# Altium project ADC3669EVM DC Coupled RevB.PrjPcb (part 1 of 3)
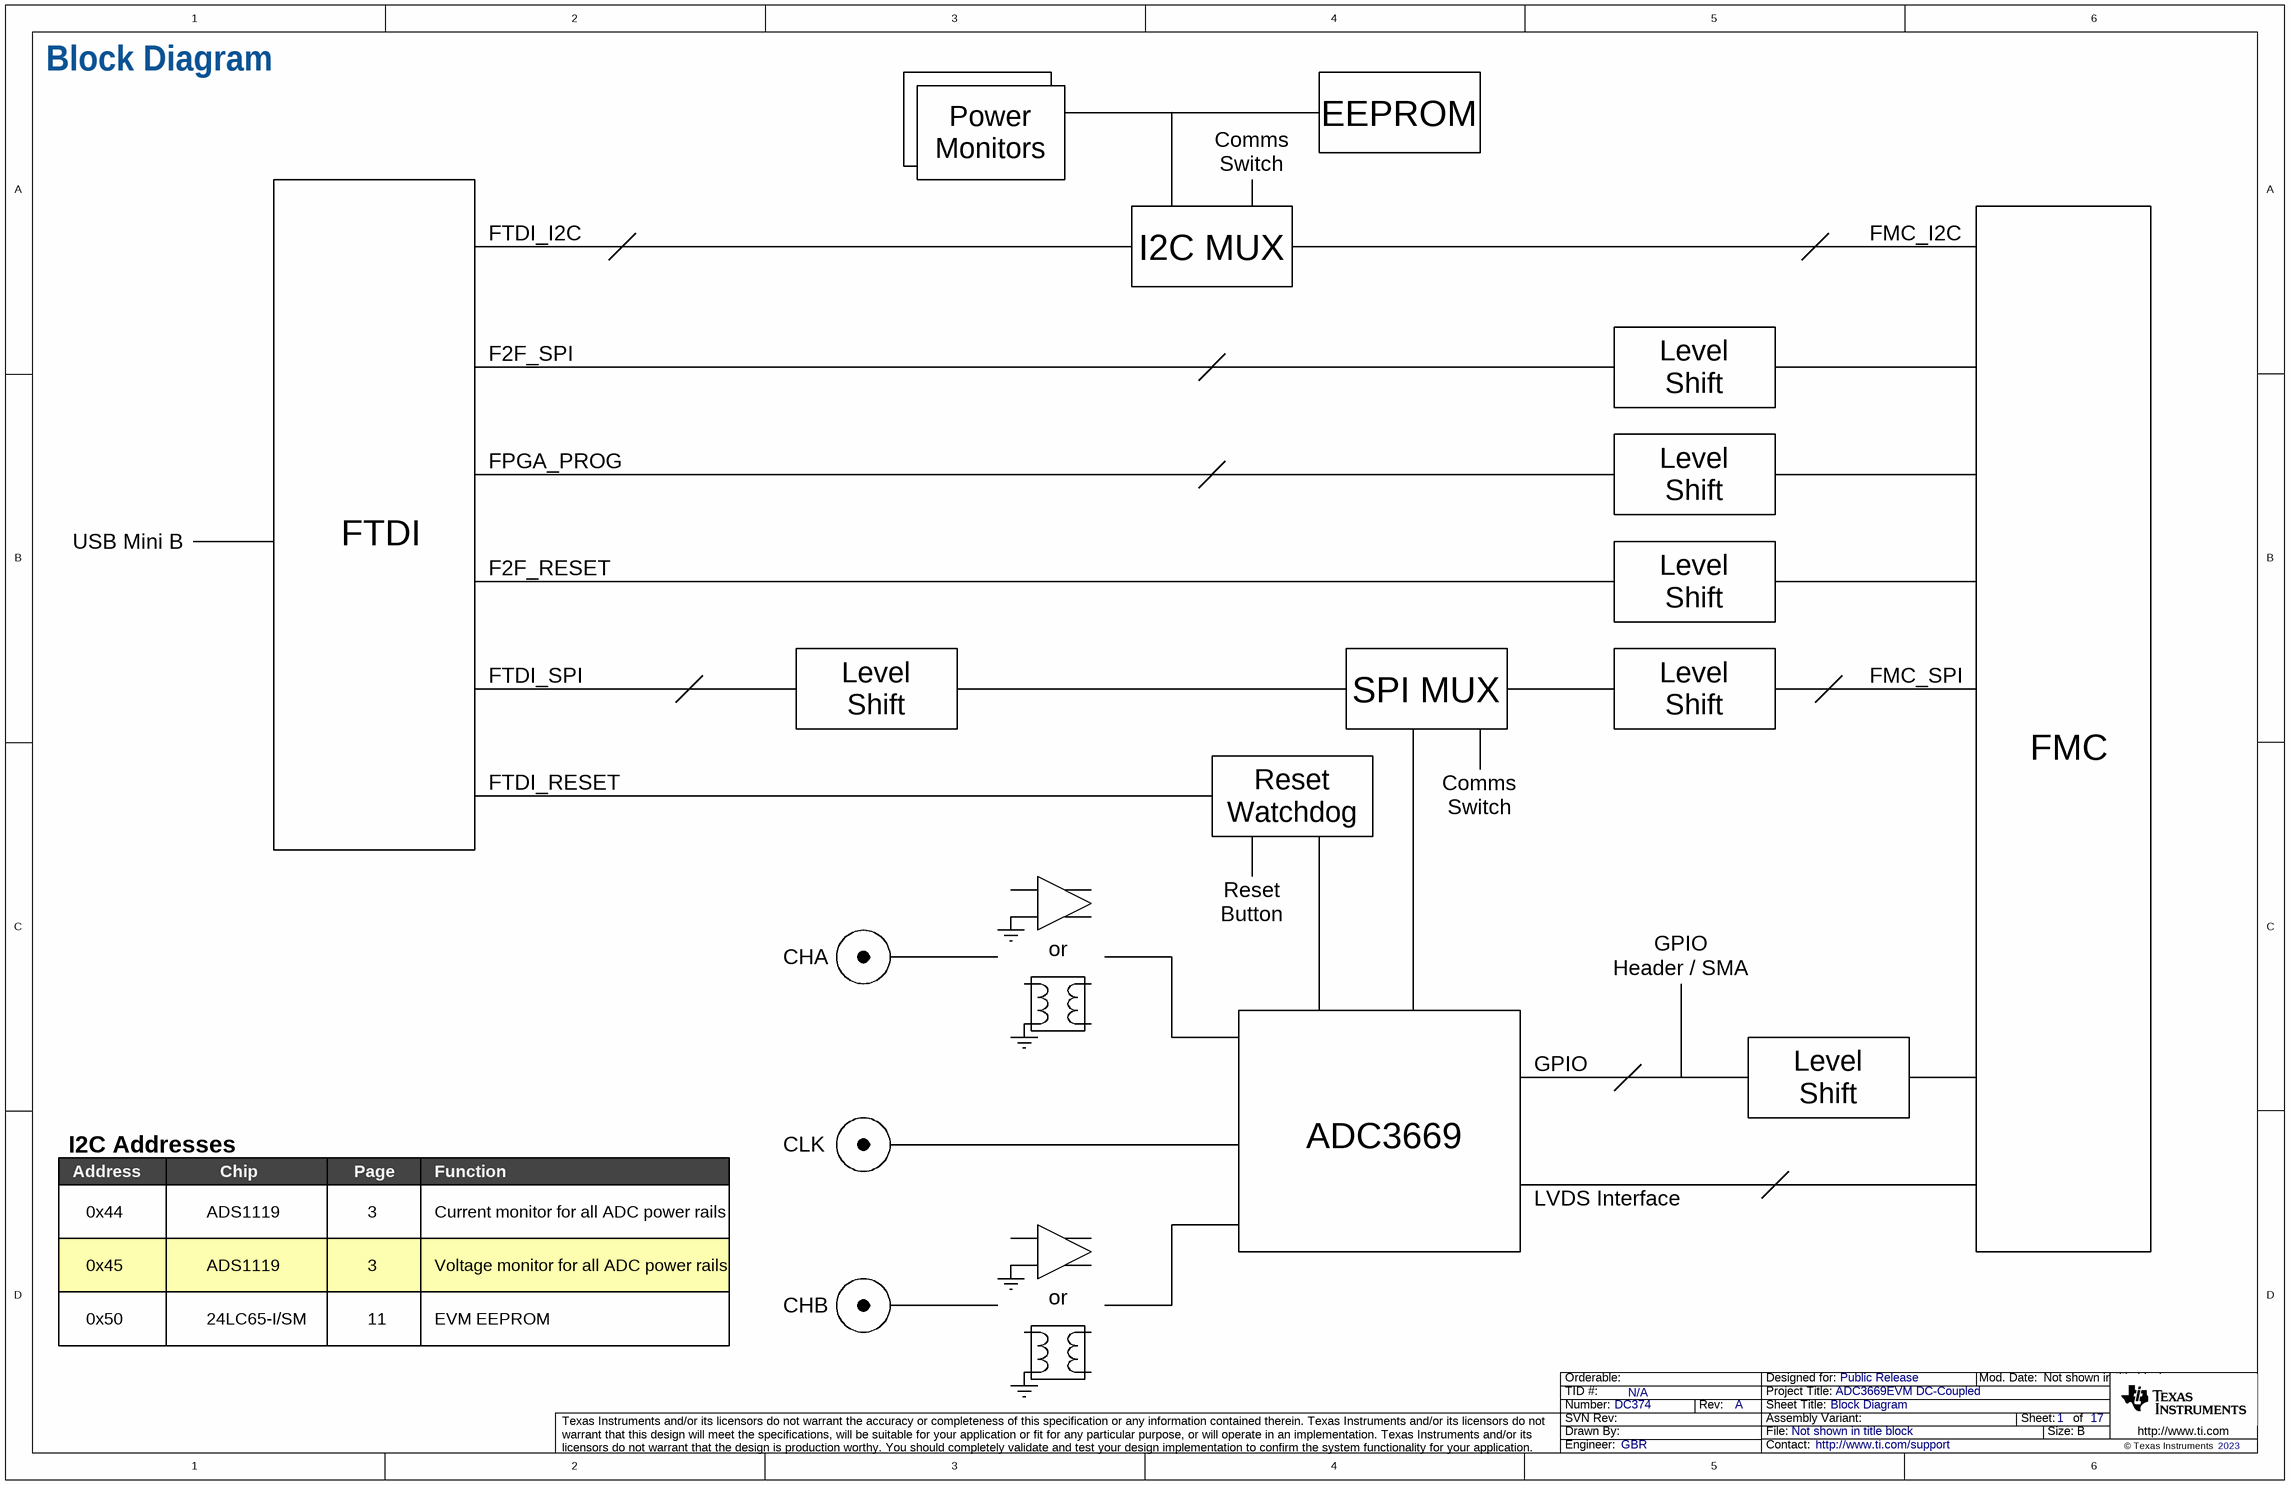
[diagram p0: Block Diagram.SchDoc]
CopyrightYear: 2023; PCB_Layout: GBR; PCB_Rev: A; PRJ_Customer: Public Release; PRJ_Engineer: GBR; PRJ_Number: DC374; PRJ_Title: ADC3669EVM DC-Coupled; SCH_Rev: A; TechSupport: http://www.ti.com/support; TID: N/A
17 sheets, 549 parts. Net scope: flat (ports and power ports of the same name join across sheets).
Board file: ADC3669EVM DC-Coupled RevB.PcbDoc
Sheets:
  Block Diagram.SchDoc
  Power Tree.SchDoc
  EVM Power.SchDoc
  ADC Power DC-DC.SchDoc
  ADC Power.SchDoc
  LMH Power DC-DC.SchDoc
  LMH Power LDO.SchDoc
  ADC IO.SchDoc
  ADC Analog Input.SchDoc
  Amplifier.SchDoc
  FMC Sections 1-7 .SchDoc
  FMC Sections 8-14.SchDoc
  FTDI USB Input.SchDoc
  Comms Level Shift.SchDoc
  I2C SPI Mux.SchDoc
  Hardware.SchDoc
  Revision History.SchDoc

## Sheet Block Diagram.SchDoc: Block Diagram
size 431 x 279 mm; Date: Not shown in title block; ApprovedBy: Not shown in title block; CheckedBy: Not shown in title block; Author: Not shown in title block; CompanyName: Not shown in title block; Engineer: Not shown in title block; Organization: Not shown in title block; Address1: Not shown in title block; Address2: Not shown in title block; Address3: Not shown in title block; Address4: Not shown in title block; DocumentNumber: 1; Revision: Use project parameter SCH_Rev; SheetNumber: 1; SheetTotal: 17; PageSetup: Record=PageOptions¦CenterHorizontal=True¦CenterVertical=True¦PrintScale=1.00¦XCorrection=1.00¦YCorrection=1.00¦PrintKind=0¦BorderSize=5000000¦LeftOffset=0¦BottomOffset=0¦Orientation=2¦PaperLength=1000¦PaperWidth=1000¦Scale=100¦PaperSource=15¦PrintQuality=600¦MediaType=1¦DitherType=10¦PaperKind=Letter¦PrintScaleMode=1

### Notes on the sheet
- Power
  Monitors
- EEPROM
- Comms
  Switch
- FTDI_I2C
- I2C MUX
- FMC_I2C
- F2F_SPI
- Level
  Shift
- FPGA_PROG
- USB Mini B
- FTDI
- F2F_RESET
- FTDI_SPI
- FMC_SPI
- SPI MUX
- FMC
- FTDI_RESET
- Reset
  Watchdog
- CHA
- or
- Reset
  Button
- GPIO
  Header / SMA
- GPIO
- Address
- I2C Addresses
- Chip
- Page
- Function
- CLK
- ADC3669
- 0x44
- ADS1119
- 3
- Current monitor for all ADC power rails
- LVDS Interface
- 0x45
- Voltage monitor for all ADC power rails
- 0x50
- 24LC65-I/SM
- 11
- EVM EEPROM
- CHB

## Sheet Power Tree.SchDoc
size 431 x 279 mm; Date: Not shown in title block; ApprovedBy: Not shown in title block; CheckedBy: Not shown in title block; Author: Not shown in title block; CompanyName: Not shown in title block; Engineer: Not shown in title block; Organization: Not shown in title block; Address1: Not shown in title block; Address2: Not shown in title block; Address3: Not shown in title block; Address4: Not shown in title block; DocumentNumber: 1; Revision: Use project parameter SCH_Rev; SheetNumber: 2; SheetTotal: 17; PageSetup: Record=PageOptions¦CenterHorizontal=True¦CenterVertical=True¦PrintScale=1.00¦XCorrection=1.00¦YCorrection=1.00¦PrintKind=0¦BorderSize=5000000¦LeftOffset=0¦BottomOffset=0¦Orientation=2¦PaperLength=1000¦PaperWidth=1000¦Scale=100¦PaperSource=15¦PrintQuality=600¦MediaType=1¦DitherType=10¦PaperKind=Letter¦PrintScaleMode=1
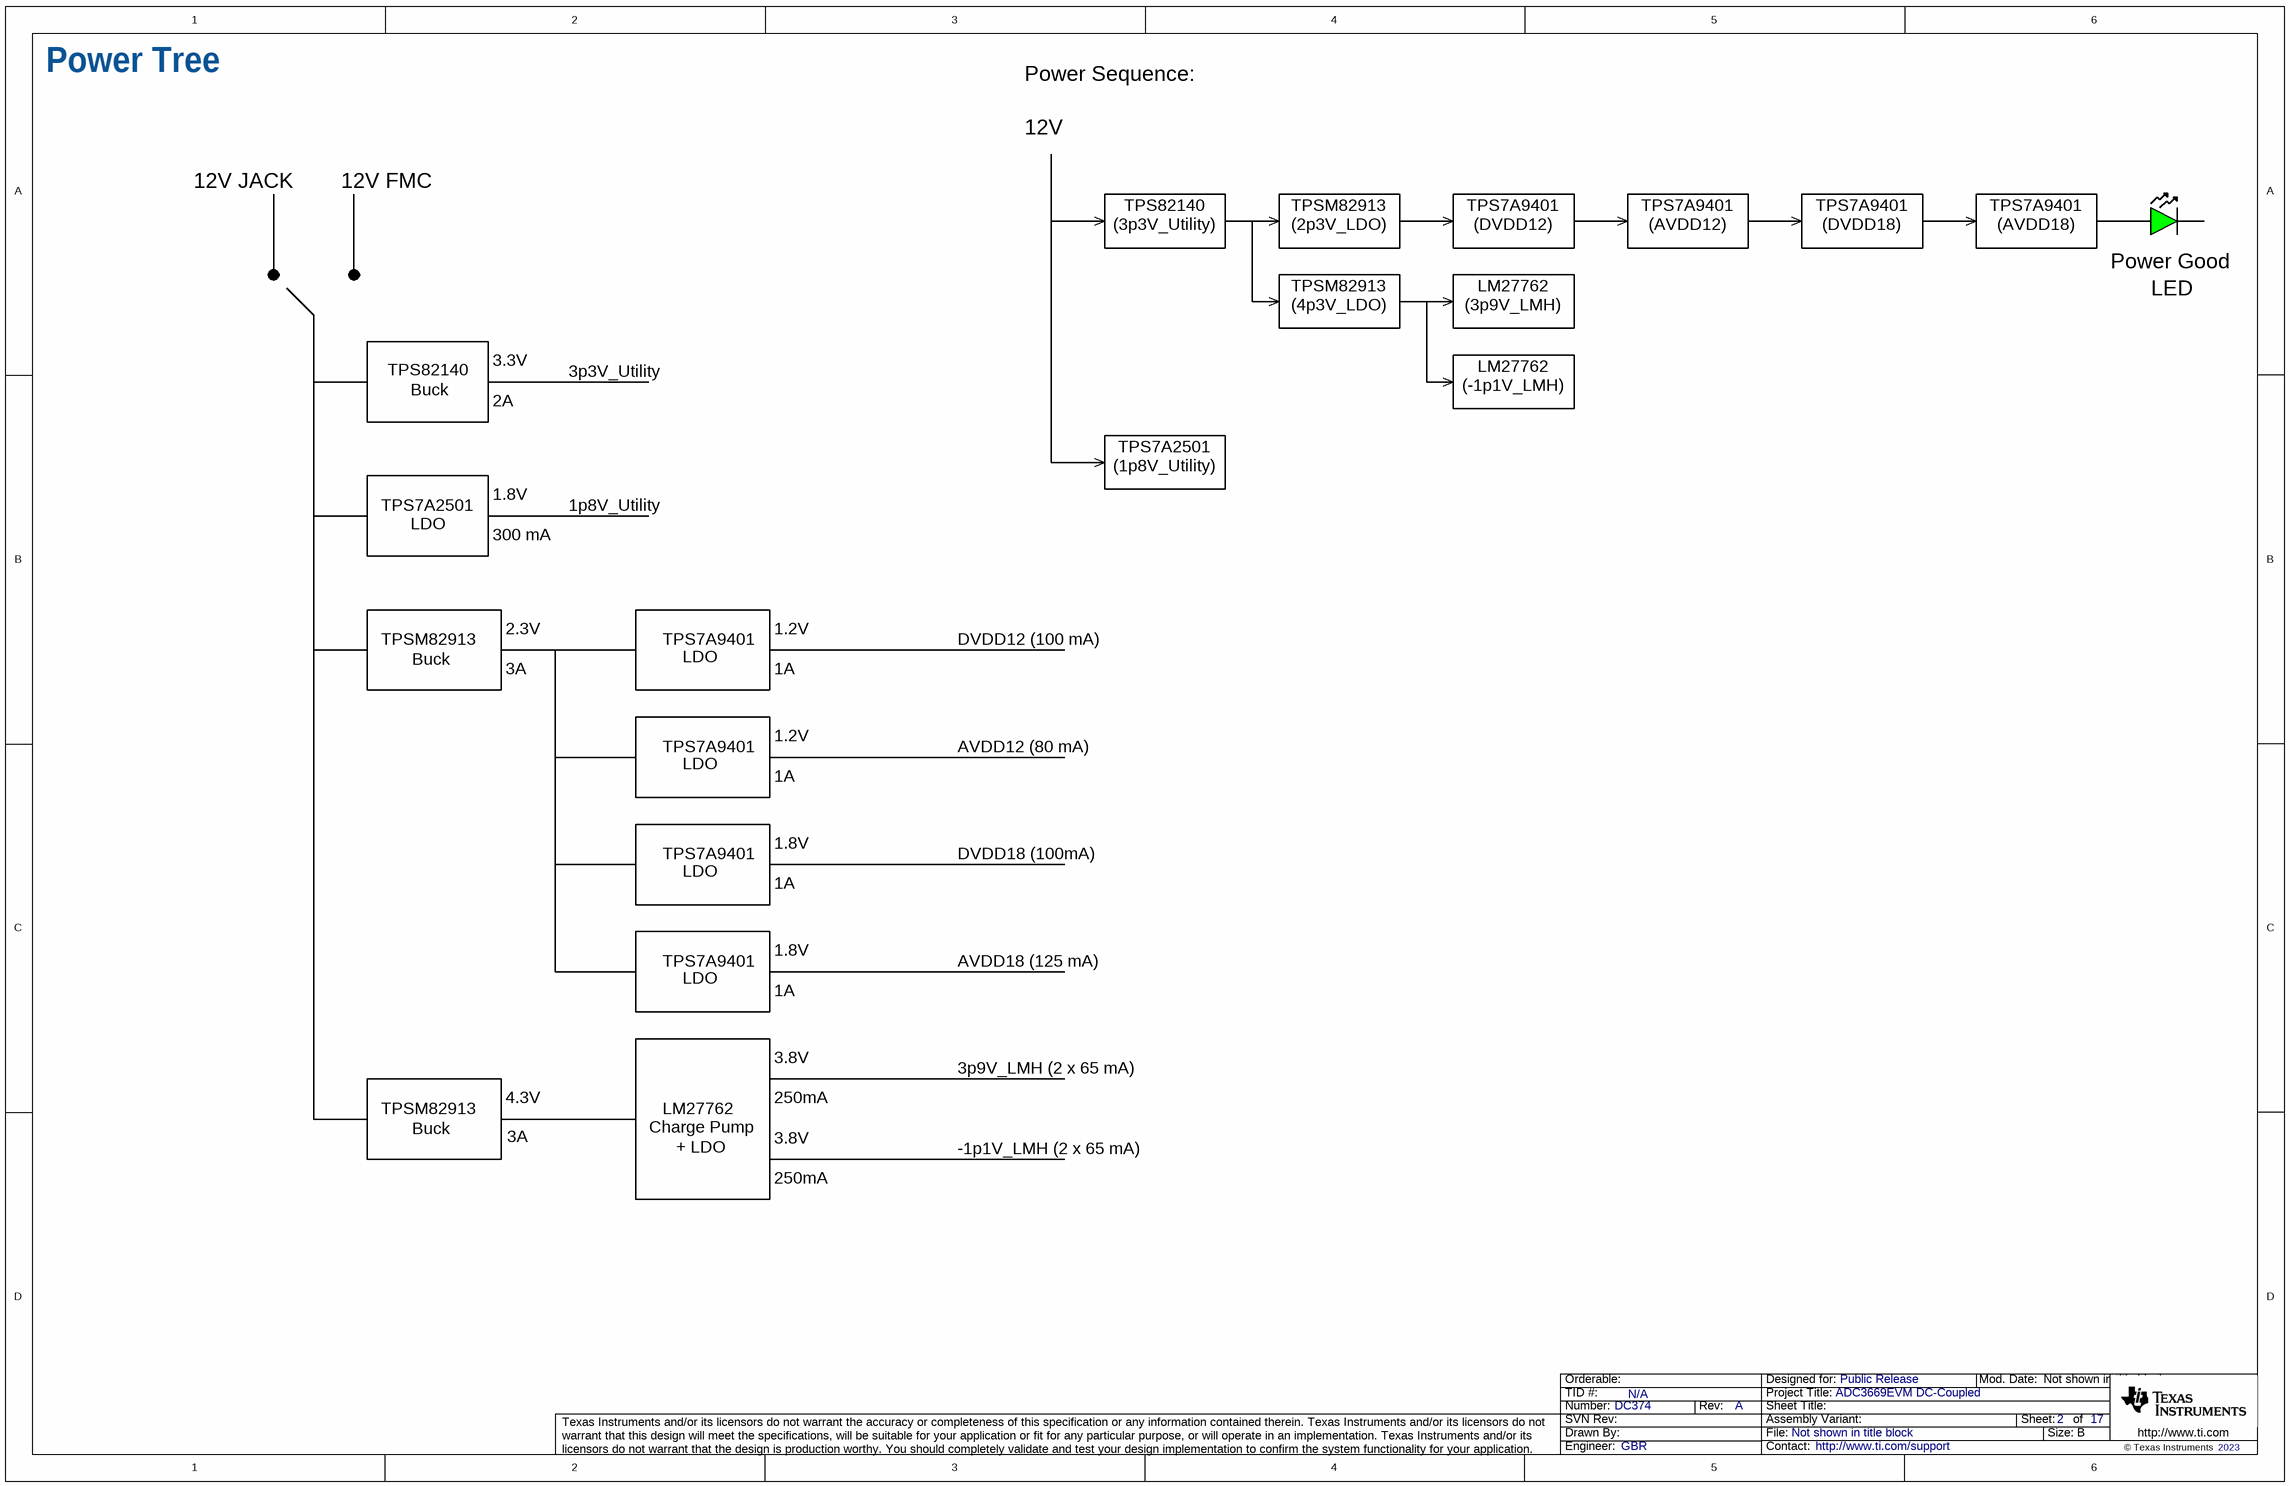
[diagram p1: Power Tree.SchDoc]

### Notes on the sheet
- Power Tree
- Power Sequence:
- 12V
- 12V JACK
- 12V FMC
- TPS82140
  (3p3V_Utility)
- TPSM82913
  (2p3V_LDO)
- TPS7A9401
  (DVDD12)
- TPS7A9401
  (AVDD12)
- TPS7A9401
  (DVDD18)
- TPS7A9401
  (AVDD18)
- Power Good
- LED
- 3.3V
- TPSM82913
  (4p3V_LDO)
- LM27762
  (3p9V_LMH)
- TPS82140
- Buck
- 2A
- 3p3V_Utility
- LM27762
  (-1p1V_LMH)
- 1.8V
- TPS7A2501
  (1p8V_Utility)
- TPS7A2501
- LDO
- 300 mA
- 1p8V_Utility
- 2.3V
- 1.2V
- TPSM82913
- 3A
- TPS7A9401
- 1A
- DVDD12 (100 mA)
- AVDD12 (80 mA)
- DVDD18 (100mA)
- AVDD18 (125 mA)
- 4.3V
- 250mA
- 3.8V
- 3p9V_LMH (2 x 65 mA)
- Charge Pump
- LM27762
- + LDO
- -1p1V_LMH (2 x 65 mA)

## Sheet EVM Power.SchDoc: EVM Power
size 431 x 279 mm; Date: Not shown in title block; ApprovedBy: Not shown in title block; CheckedBy: Not shown in title block; Author: Not shown in title block; CompanyName: Not shown in title block; Engineer: Not shown in title block; Organization: Not shown in title block; Address1: Not shown in title block; Address2: Not shown in title block; Address3: Not shown in title block; Address4: Not shown in title block; DocumentNumber: 1; Revision: Use project parameter SCH_Rev; SheetNumber: 3; SheetTotal: 17; PageSetup: Record=PageOptions¦CenterHorizontal=True¦CenterVertical=True¦PrintScale=1.00¦XCorrection=1.00¦YCorrection=1.00¦PrintKind=0¦BorderSize=5000000¦LeftOffset=0¦BottomOffset=0¦Orientation=2¦PaperLength=1000¦PaperWidth=1000¦Scale=100¦PaperSource=15¦PrintQuality=600¦MediaType=1¦DitherType=10¦PaperKind=Letter¦PrintScaleMode=1
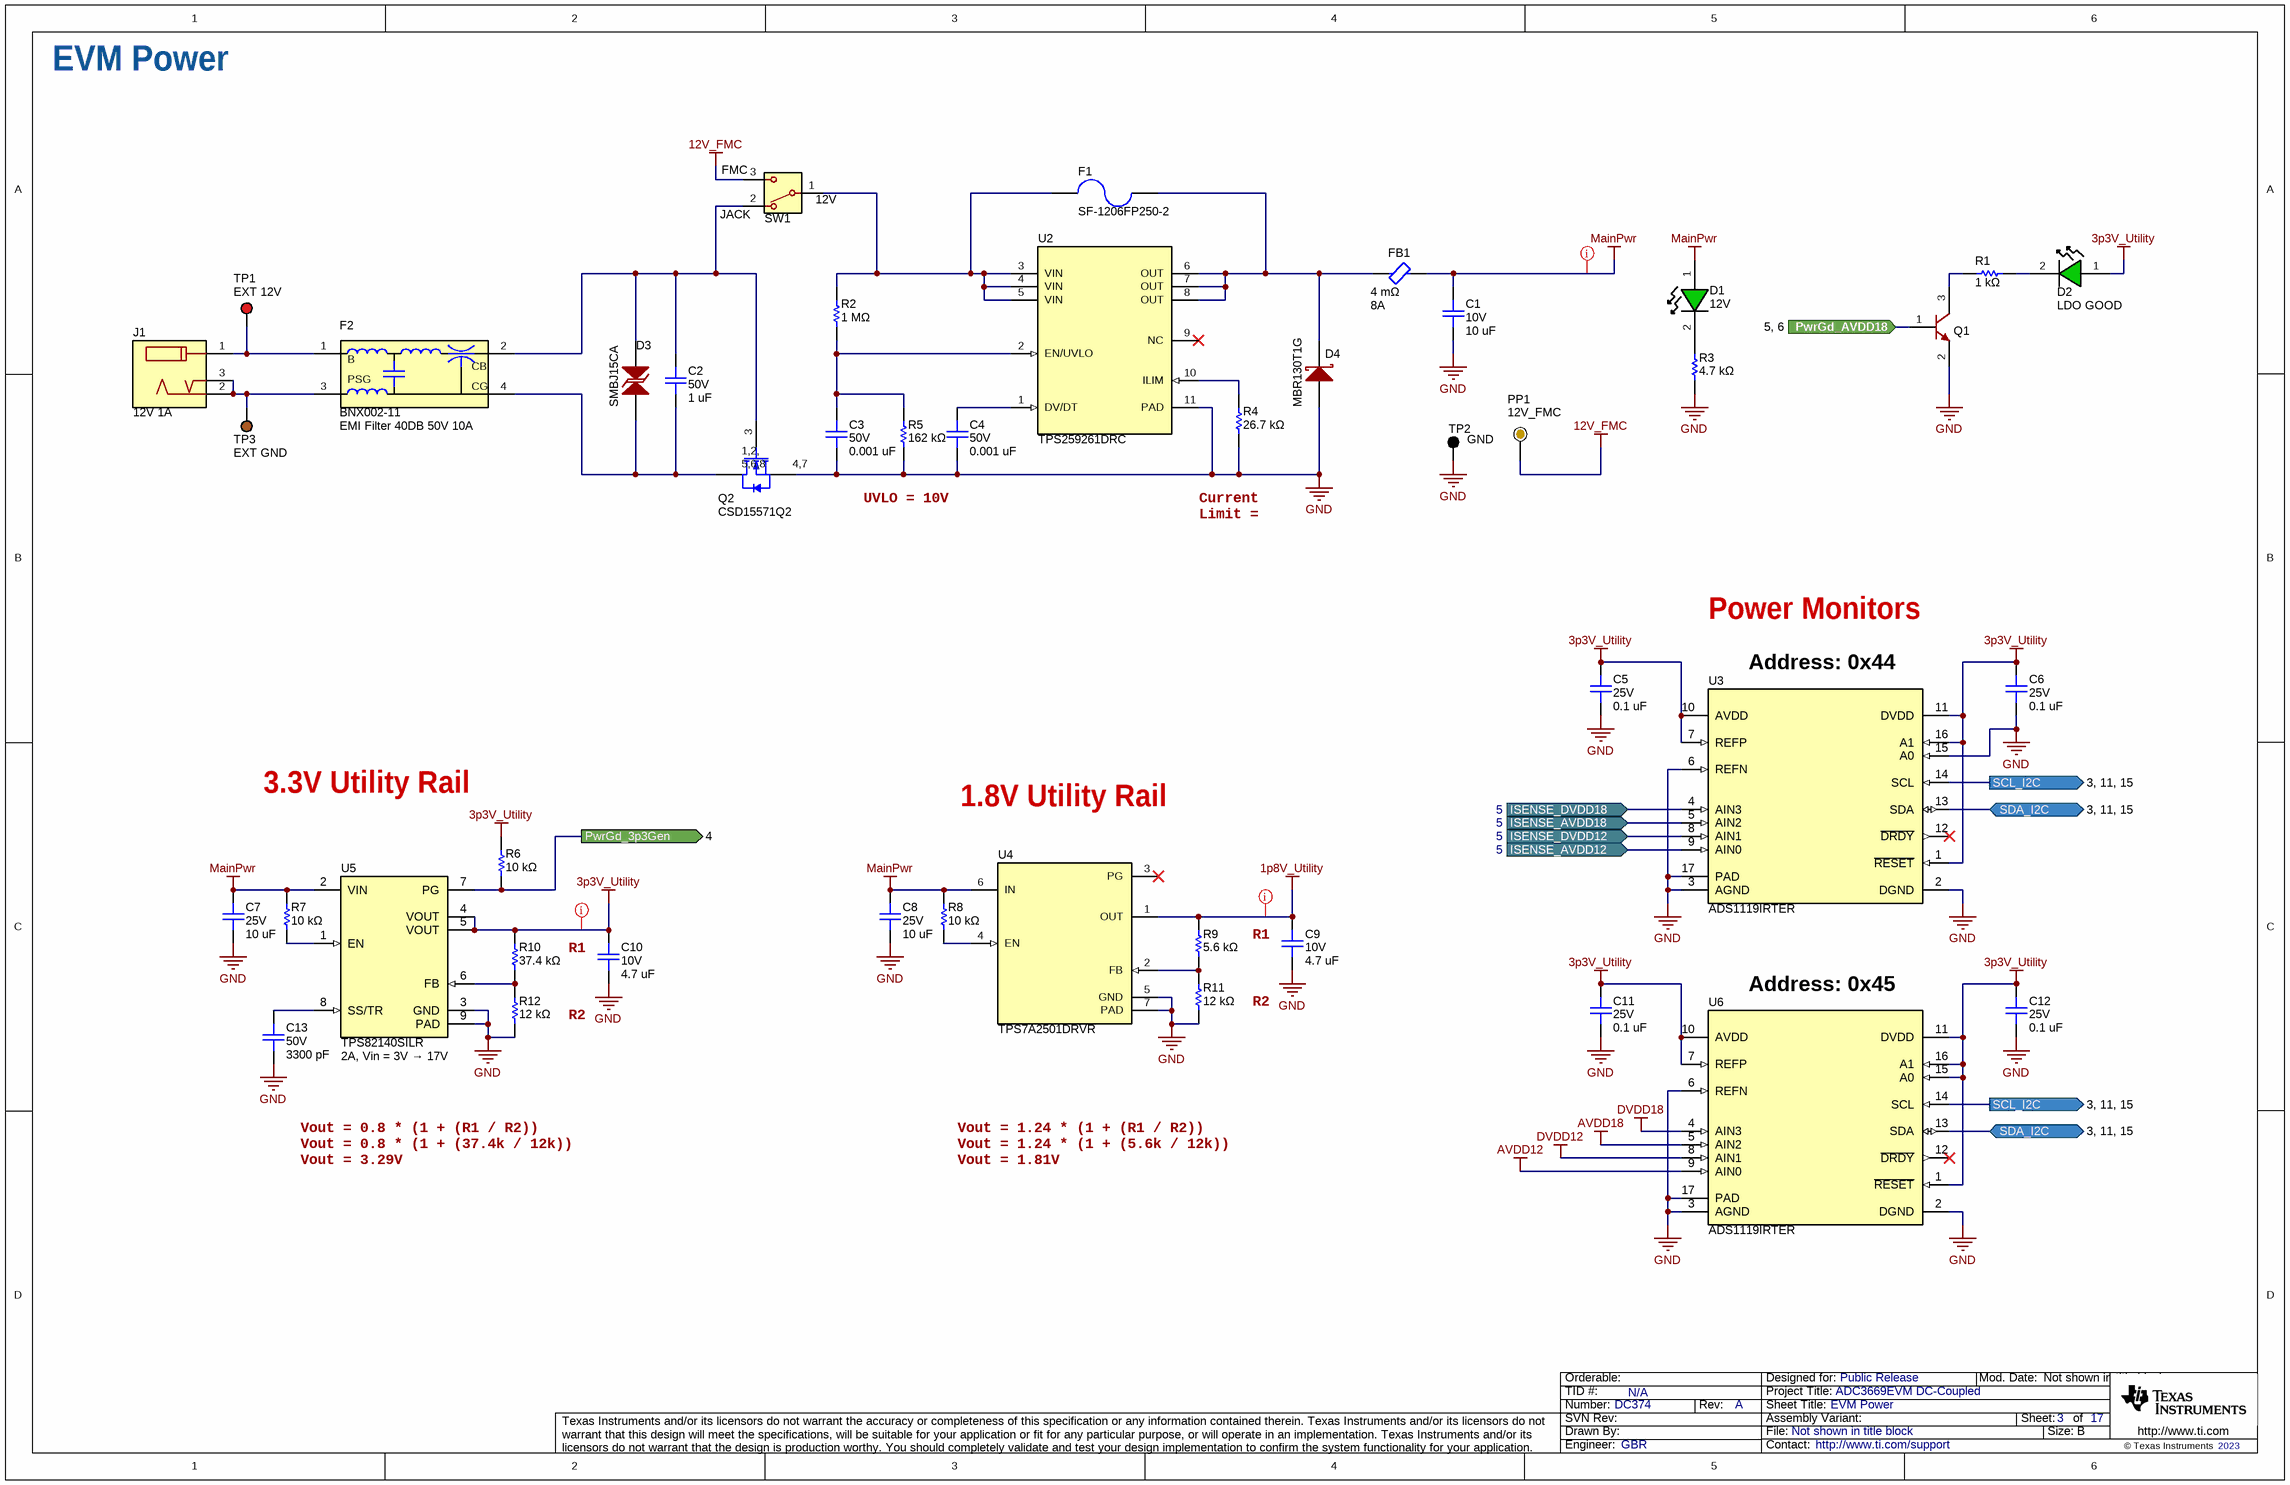
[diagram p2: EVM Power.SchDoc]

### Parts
C1  value 10 uF  Voltage - Rated: 10V  [0402L_cap]  (hidden comment: 0402ZD106MAT2A)
C2  value 1 uF  Voltage - Rated: 50V  [0603L_cap]  (hidden comment: 06035C105KAT2A)
C3  value 0.001 uF  Voltage - Rated: 50V  [0603L_cap]  (hidden comment: CGA3E2X7R1H102K080AA)
C4  value 0.001 uF  Voltage - Rated: 50V  [0603L_cap]  (hidden comment: CGA3E2X7R1H102K080AA)
C5  value 0.1 uF  Voltage - Rated: 25V  [0402L_cap]  (hidden comment: C1005X5R1E104K050BC)
C6  value 0.1 uF  Voltage - Rated: 25V  [0402L_cap]  (hidden comment: C1005X5R1E104K050BC)
C7  value 10 uF  Voltage - Rated: 25V  [0805L_cap]  (hidden comment: 08053D106KAT4A)
C8  value 10 uF  Voltage - Rated: 25V  [0805L_cap]  (hidden comment: 08053D106KAT4A)
C9  value 4.7 uF  Voltage - Rated: 10V  [0402L_cap]  (hidden comment: C1005X5R1A475K050BE)
C10  value 4.7 uF  Voltage - Rated: 10V  [0402L_cap]  (hidden comment: C1005X5R1A475K050BE)
C11  value 0.1 uF  Voltage - Rated: 25V  [0402L_cap]  (hidden comment: C1005X5R1E104K050BC)
C12  value 0.1 uF  Voltage - Rated: 25V  [0402L_cap]  (hidden comment: C1005X5R1E104K050BC)
C13  value 3300 pF  Voltage - Rated: 50V  [0402L_cap]  (hidden comment: 04025C332K4T2A)
D1  Text1: 12V  [LED_LTST-C190-Green]  (hidden comment: LTST-C191TGKT)
D2  Text1: LDO GOOD  [LED_LTST-C190-Green]  (hidden comment: LTST-C191TGKT)
D3  SMBJ15CA  [SMBJ15CA]
D4  MBR130T1G  [SOD-123]
F1  SF-1206FP250-2  [SF-1206F500M-2_1206]
F2  BNX002-11  Text1: EMI Filter 40DB 50V 10A  [FIL_BNX002-11]
FB1  Current: 8A  DCR: 4 mΩ  [0603L]  (hidden comment: BLE18PS080SN1D)
J1  Text1: 12V 1A  [RAPC722X]  (hidden comment: RAPC722X)
PP1  Text1: 12V_FMC  [ProbePoint_TH_40mil]  (hidden comment: Probe Point)  (no BOM)
Q1  MMBT3904WT1G  [SOT-323]  (value not drawn)
Q2  CSD15571Q2  [DQK0006C]
R1  value 1 kΩ  [0402L]  (hidden comment: ERA-2AED102X)
R2  value 1 MΩ  [0402L]  (hidden comment: ERJ-2RKF1004X)
R3  value 4.7 kΩ  [0402L]  (hidden comment: ERJ-H2RF4701X)
R4  value 26.7 kΩ  [0402L]  (hidden comment: ERA-2APB2672X)
R5  value 162 kΩ  [0402L]  (hidden comment: ERJ-2RKF1623X)
R6  value 10 kΩ  [0402L]  (hidden comment: ERJ-2RKF1002X)
R7  value 10 kΩ  [0402L]  (hidden comment: ERJ-2RKF1002X)
R8  value 10 kΩ  [0402L]  (hidden comment: ERJ-2RKF1002X)
R9  value 5.6 kΩ  [0402L]  (hidden comment: ERA-2APB562X)
R10  value 37.4 kΩ  [0402L]  (hidden comment: ERA-2AEB3742X)
R11  value 12 kΩ  [0402L]  (hidden comment: ERA-2ARB123X)
R12  value 12 kΩ  [0402L]  (hidden comment: ERA-2ARB123X)
SW1  Text1: 12V  Text2: JACK  Text3: FMC  [450301014042]  (hidden comment: cmp00353)
TP1  Text1: EXT 12V  [Keystone5010]  (hidden comment: 5010)
TP2  Text1: GND  [Keystone5011]  (hidden comment: cmp00041)
TP3  Text1: EXT GND  [Keystone5125]  (hidden comment: 5125)
U2  TPS259261DRC  [DRC0010J]
U3  ADS1119IRTER  [RTE0016D]
U4  TPS7A2501DRVR  [DRV0006A]
U5  TPS82140SILR  Text1: 2A, Vin = 3V → 17V  [SIL0008D]
U6  ADS1119IRTER  [RTE0016D]

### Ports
ISENSE_AVDD12 (in, see 5), ISENSE_AVDD18 (in, see 5), ISENSE_DVDD12 (in, see 5), ISENSE_DVDD18 (in, see 5), PwrGd_3p3Gen (out, see 4), PwrGd_AVDD18 (in, see 5, 6), SCL_I2C (out, see 3, 11, 15), SDA_I2C (bidir, see 3, 11, 15)

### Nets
1p8V_Utility: C9.2 R9.2 U4.1(OUT)
3p3V_Utility: C5.2 C6.2 C10.2 C11.2 C12.2 D2.1(A) R6.2 R10.2 U3.1(~{RESET}) U3.7(REFP) U3.10(AVDD) U3.11(DVDD) U3.16(A1) U5.4(VOUT) U5.5(VOUT) U6.1(~{RESET}) U6.7(REFP) U6.10(AVDD) U6.11(DVDD) U6.15(A0) U6.16(A1)
12V_FMC: PP1.1 SW1.3
AVDD12: U6.9(AIN0)
AVDD18: U6.5(AIN2)
DVDD12: U6.8(AIN1)
DVDD18: U6.4(AIN3)
GND: C1.1 C3.1 C4.1 C5.1 C6.1 C7.1 C8.1 C9.1 C10.1 C11.1 C12.1 C13.1 D4.2(A) Q1.2(E) Q2.4,7(S) R3.1 R4.1 R5.1 R11.1 R12.1 TP2.1 U2.11(PAD) U3.2(DGND) U3.3(AGND) U3.6(REFN) U3.15(A0) U3.17(PAD) U4.5(GND) U4.7(PAD) U5.3(GND) U5.9(PAD) U6.2(DGND) U6.3(AGND) U6.6(REFN) U6.17(PAD)
MainPwr: C1.2 C7.2 C8.2 D1.1(A) FB1.2 R7.2 R8.2 U4.6(IN) U5.2(VIN)
ISENSE_AVDD12: U3.9(AIN0) ; port ISENSE_AVDD12
ISENSE_AVDD18: U3.5(AIN2) ; port ISENSE_AVDD18
ISENSE_DVDD12: U3.8(AIN1) ; port ISENSE_DVDD12
ISENSE_DVDD18: U3.4(AIN3) ; port ISENSE_DVDD18
PwrGd_3p3Gen: R6.1 U5.7(PG) ; port PwrGd_3p3Gen
PwrGd_AVDD18: Q1.1(B) ; port PwrGd_AVDD18
SCL_I2C: U3.14(SCL) U6.14(SCL) ; port SCL_I2C
SDA_I2C: U3.13(SDA) U6.13(SDA) ; port SDA_I2C
NetC2_1: C2.1 D3.2 F2.2(CB) Q2.3(G) SW1.2(COMM)
NetC2_2: C2.2 D3.1 F2.4(CG) Q2.1,2,5,6,8(D)
NetC3_2: C3.2 R2.1 R5.2 U2.2(EN/UVLO)
NetC4_2: C4.2 U2.1(DV/DT)
NetC13_2: C13.2 U5.8(SS/TR)
NetD1_2: D1.2(K) R3.2
NetD2_2: D2.2(K) R1.1
NetD4_1: D4.1(K) F1.1 FB1.1 U2.6(OUT) U2.7(OUT) U2.8(OUT)
NetF1_2: F1.2 R2.2 SW1.1 U2.3(VIN) U2.4(VIN) U2.5(VIN)
NetF2_1: F2.1(B) J1.1 TP1.1
NetF2_3: F2.3(PSG) J1.2 J1.3 TP3.1
NetQ1_3: Q1.3(C) R1.2
NetR4_2: R4.2 U2.10(ILIM)
NetR7_1: R7.1 U5.1(EN)
NetR8_1: R8.1 U4.4(EN)
NetR9_1: R9.1 R11.2 U4.2(FB)
NetR10_1: R10.1 R12.2 U5.6(FB)

Not connected (* = marked no-connect by the designer): U2 9(NC)*; U3 12(~{DRDY})*; U4 3(PG)*; U6 12(~{DRDY})*

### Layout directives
net class Power: MainPwr
net class Power; net class GenPwr: 1p8V_Utility, 3p3V_Utility

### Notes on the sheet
- UVLO = 10V
- Current Limit = 1.5A
- Power Monitors
- (near U3) Address: 0x44
- (near R6) 3.3V Utility Rail
- 1.8V Utility Rail
- (near C10) R1
- (near C9) R1
- R2
- (near U6) Address: 0x45
- Vout = 0.8 * (1 + (R1 / R2))
  Vout = 0.8 * (1 + (37.4k / 12k))
  Vout = 3.29V
- Vout = 1.24 * (1 + (R1 / R2))
  Vout = 1.24 * (1 + (5.6k / 12k))
  Vout = 1.81V

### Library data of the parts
C1 = capcc09406: CAP CER 10UF 10V X5R 0402; Manufacturer: KYOCERA AVX; CompType: Capacitor Ceramic; Tolerance: ±20%; SizeX_mm: 1; SizeY_mm: 0.5; SizeZ_mm: 0.7
C2 = capcc02732: CAP CER 1UF 50V X7R 0603; Manufacturer: KYOCERA AVX; CompType: Capacitor Ceramic; Tolerance: ±10%; SizeX_mm: 1.6; SizeY_mm: 0.81; SizeZ_mm: 0.5
C3 C4 = capcc03751: CAP CER 1000PF 50V X7R 0603; Manufacturer: TDK Corporation; CompType: Capacitor Ceramic; Tolerance: ±10%; SizeX_mm: 1.6; SizeY_mm: 0.8; SizeZ_mm: 0.9
C5 C6 C11 C12 = capcc01263: CAP CER 0.1UF 25V X5R 0402; Manufacturer: TDK Corporation; CompType: Capacitor Ceramic; Tolerance: ±10%; SizeX_mm: 1; SizeY_mm: 0.5; SizeZ_mm: 0.55
C7 C8 = capcc03515: CAP CER 10UF 25V X5R 0805; Manufacturer: KYOCERA AVX; CompType: Capacitor Ceramic; Tolerance: ±10%; SizeX_mm: 2.01; SizeY_mm: 1.25; SizeZ_mm: 1.52
C9 C10 = capcc03139: CAP CER 4.7UF 10V X5R 0402; Manufacturer: TDK Corporation; CompType: Capacitor Ceramic; Tolerance: ±10%; SizeX_mm: 1; SizeY_mm: 0.5; SizeZ_mm: 0.7
C13 = capcc04791: CAP CER 3300PF 50V X7R 0402; Manufacturer: KYOCERA AVX; CompType: Capacitor Ceramic; Tolerance: ±10%; SizeX_mm: 1; SizeY_mm: 0.5; SizeZ_mm: 0.56
D1 D2 = cmp00247: LED GREEN CLEAR CHIP SMD; Manufacturer: Lite-On Inc.; Current Rating (Amps): 20mA; Voltage - Forward (Vf) (Typ): 3.2V; SizeX_mm: 1.6; SizeY_mm: 0.8; SizeZ_mm: 0.65
D3 = cmp00440: 24.4V Clamp 24.6A Ipp Tvs Diode; Manufacturer: Littlefuse; CompType: Diode TVS
D4 = cmp00438: DIODE SCHOTTKY 30V 1A SOD123; Manufacturer: Onsemi; Alt Manufacturer: Rohm Semiconductor; Alt PartNumber: RB160M-30TR
F1 = cmp00082: FUSE BOARD MOUNT 2.5A 32VDC 1206; Manufacturer: Bourns Inc.; Voltage Rating - DC: 32 V; SizeX_mm: 3.1; SizeY_mm: 1.55; SizeZ_mm: 0.6
F2 = cmp00325: EMI Filter Circuits 40 DB 50V 10A; Manufacturer: Murata Electronics
FB1 = dcp00004: 8.5 Ohms @ 100 MHz 1 Power Line Ferrite Bead 0603 (1608 Metric) 8A 4mOhm; Manufacturer: Murata; Impedance: 8.5 Ω; SizeX_mm: 1.6; SizeY_mm: 0.8
J1 = RAPC722X: Power Jack, mini, 2.1mm OD, R/A, TH; Manufacturer: Switchcraft; UniqueID: cmp00022
PP1 = Probe Point: Probe Point that can be used in lue of a test point; UniqueID: cmp00025
Q1 = cmp00439: Bipolar (BJT) Transistor NPN 40 V 200 mA 300MHz 300 mW; PartNumber: SMMBT3904LT1G; Manufacturer: Onsemi
Q2 = cmp00159: MOSFET, N-CH, 20 V, 10 A; Manufacturer: Texas Instruments; CompType: FET
R1 = RSMD040200005: RES SMD 1K OHM 0.5% 1/16W 0402; Manufacturer: Panasonic Electronic Components; CompType: Resistor SMD; Power (Watts): 0.063W, 1/16W; Temperature Coefficient: ±25ppm/°C; SizeX_mm: 1; SizeY_mm: 0.5; SizeZ_mm: 0.4
R2 = RSMD040200026: RES SMD 1M OHM 1% 1/10W 0402; Manufacturer: Panasonic Electronic Components; CompType: Resistor SMD; Power (Watts): 0.1W, 1/10W; Temperature Coefficient: ±100ppm/°C; SizeX_mm: 1; SizeY_mm: 0.5; SizeZ_mm: 0.4
R3 = RSMD040202592: RES 4.7K OHM 1% 1/10W 0402; Manufacturer: Panasonic Electronic Components; CompType: Resistor SMD; Power (Watts): 0.1W, 1/10W; Temperature Coefficient: ±100ppm/°C; SizeX_mm: 1; SizeY_mm: 0.5; SizeZ_mm: 0.4
R4 = RSMD040201732: RES SMD 26.7KOHM 0.1% 1/16W 0402; Manufacturer: Panasonic Electronic Components; CompType: Resistor SMD; Power (Watts): 0.063W, 1/16W; Temperature Coefficient: ±15ppm/°C; SizeX_mm: 1; SizeY_mm: 0.5; SizeZ_mm: 0.4
R5 = RSMD040200944: RES SMD 162K OHM 1% 1/10W 0402; Manufacturer: Panasonic Electronic Components; CompType: Resistor SMD; Power (Watts): 0.1W, 1/10W; Temperature Coefficient: ±100ppm/°C; SizeX_mm: 1; SizeY_mm: 0.5; SizeZ_mm: 0.4
R6-R8 = RSMD040200314: RES SMD 10K OHM 1% 1/10W 0402; Manufacturer: Panasonic Electronic Components; CompType: Resistor SMD; Power (Watts): 0.1W, 1/10W; Temperature Coefficient: ±100ppm/°C; SizeX_mm: 1; SizeY_mm: 0.5; SizeZ_mm: 0.4
R9 = RSMD040202967: RES SMD 5.6K OHM 0.1% 1/16W 0402; Manufacturer: Panasonic Electronic Components; CompType: Resistor SMD; Power (Watts): 0.063W, 1/16W; Temperature Coefficient: ±15ppm/°C; SizeX_mm: 1; SizeY_mm: 0.5; SizeZ_mm: 0.4
R10 = RSMD040202418: RES SMD 37.4KOHM 0.1% 1/16W 0402; Manufacturer: Panasonic Electronic Components; CompType: Resistor SMD; Power (Watts): 0.063W, 1/16W; Temperature Coefficient: ±25ppm/°C; SizeX_mm: 1; SizeY_mm: 0.5; SizeZ_mm: 0.4
R11 R12 = RSMD040200520: RES SMD 12K OHM 0.1% 1/16W 0402; Manufacturer: Panasonic Electronic Components; CompType: Resistor SMD; Power (Watts): 0.063W, 1/16W; Temperature Coefficient: ±10ppm/°C; SizeX_mm: 1; SizeY_mm: 0.5; SizeZ_mm: 0.4
SW1 = cmp00353: Switch Slide SPDT 12V, 500mA; Manufacturer: Wurth Elektronik
TP1 = cmp00040: Test Point, Multipurpose, Red, TH; Manufacturer: Keystone
TP2 = cmp00041: Test Point, Multipurpose, Black, TH; PartNumber: 5011; Manufacturer: Keystone
TP3 = cmp00047: Test Point, Multipurpose, Brown, TH; Manufacturer: Keystone
U2 = cmp00157: 12V, 5A, 30mΩ eFuse with Adjustable +/-15% Accurate Current Limit, DRC0010J (VSON-10); Manufacturer: Texas Instruments; Text1: Rilim=(IOL-0.7)/30µ
U3 U6 = ADS1119IRTER: 16-Bit, 4-Channel, 1-kSPS, Delta-Sigma ADC with I2C Interface, RTE0016D (WQFN-16); Alternate PartNumber: ADS1119IRTET; Alternate Manufacturer: Texas Instruments; SizeAreaWB_mm2: 16; SizeZ_mm: 0.8; SizeX_mm: 3; SizeArea_mm2: 9; AEC Qualified: N; AEC Category: Q200
U4 = cmp00251: 300-mA, 18-V, Ultra-Low IQ, Low-Dropout Linear Voltage Regulator With Power-Good; Manufacturer: Texas Instruments; CompType: LDO
U5 = TPS82140SILR: 17V Input 2A Synchronous Step-Down Converter MicroSiP Module With Integrated Inductor, SIL0008D (uSIP-8); Manufacturer: Texas Instruments; Alternate PartNumber: TPS82140SILT; CompType: Switcher

## Sheet ADC Power DC-DC.SchDoc
size 431 x 279 mm; Date: Not shown in title block; ApprovedBy: Not shown in title block; CheckedBy: Not shown in title block; Author: Not shown in title block; CompanyName: Not shown in title block; Engineer: Not shown in title block; Organization: Not shown in title block; Address1: Not shown in title block; Address2: Not shown in title block; Address3: Not shown in title block; Address4: Not shown in title block; DocumentNumber: 1; Revision: Use project parameter SCH_Rev; SheetNumber: 4; SheetTotal: 17; PageSetup: Record=PageOptions¦CenterHorizontal=True¦CenterVertical=True¦PrintScale=1.00¦XCorrection=1.00¦YCorrection=1.00¦PrintKind=0¦BorderSize=5000000¦LeftOffset=0¦BottomOffset=0¦Orientation=2¦PaperLength=1000¦PaperWidth=1000¦Scale=100¦PaperSource=15¦PrintQuality=600¦MediaType=1¦DitherType=10¦PaperKind=Letter¦PrintScaleMode=1
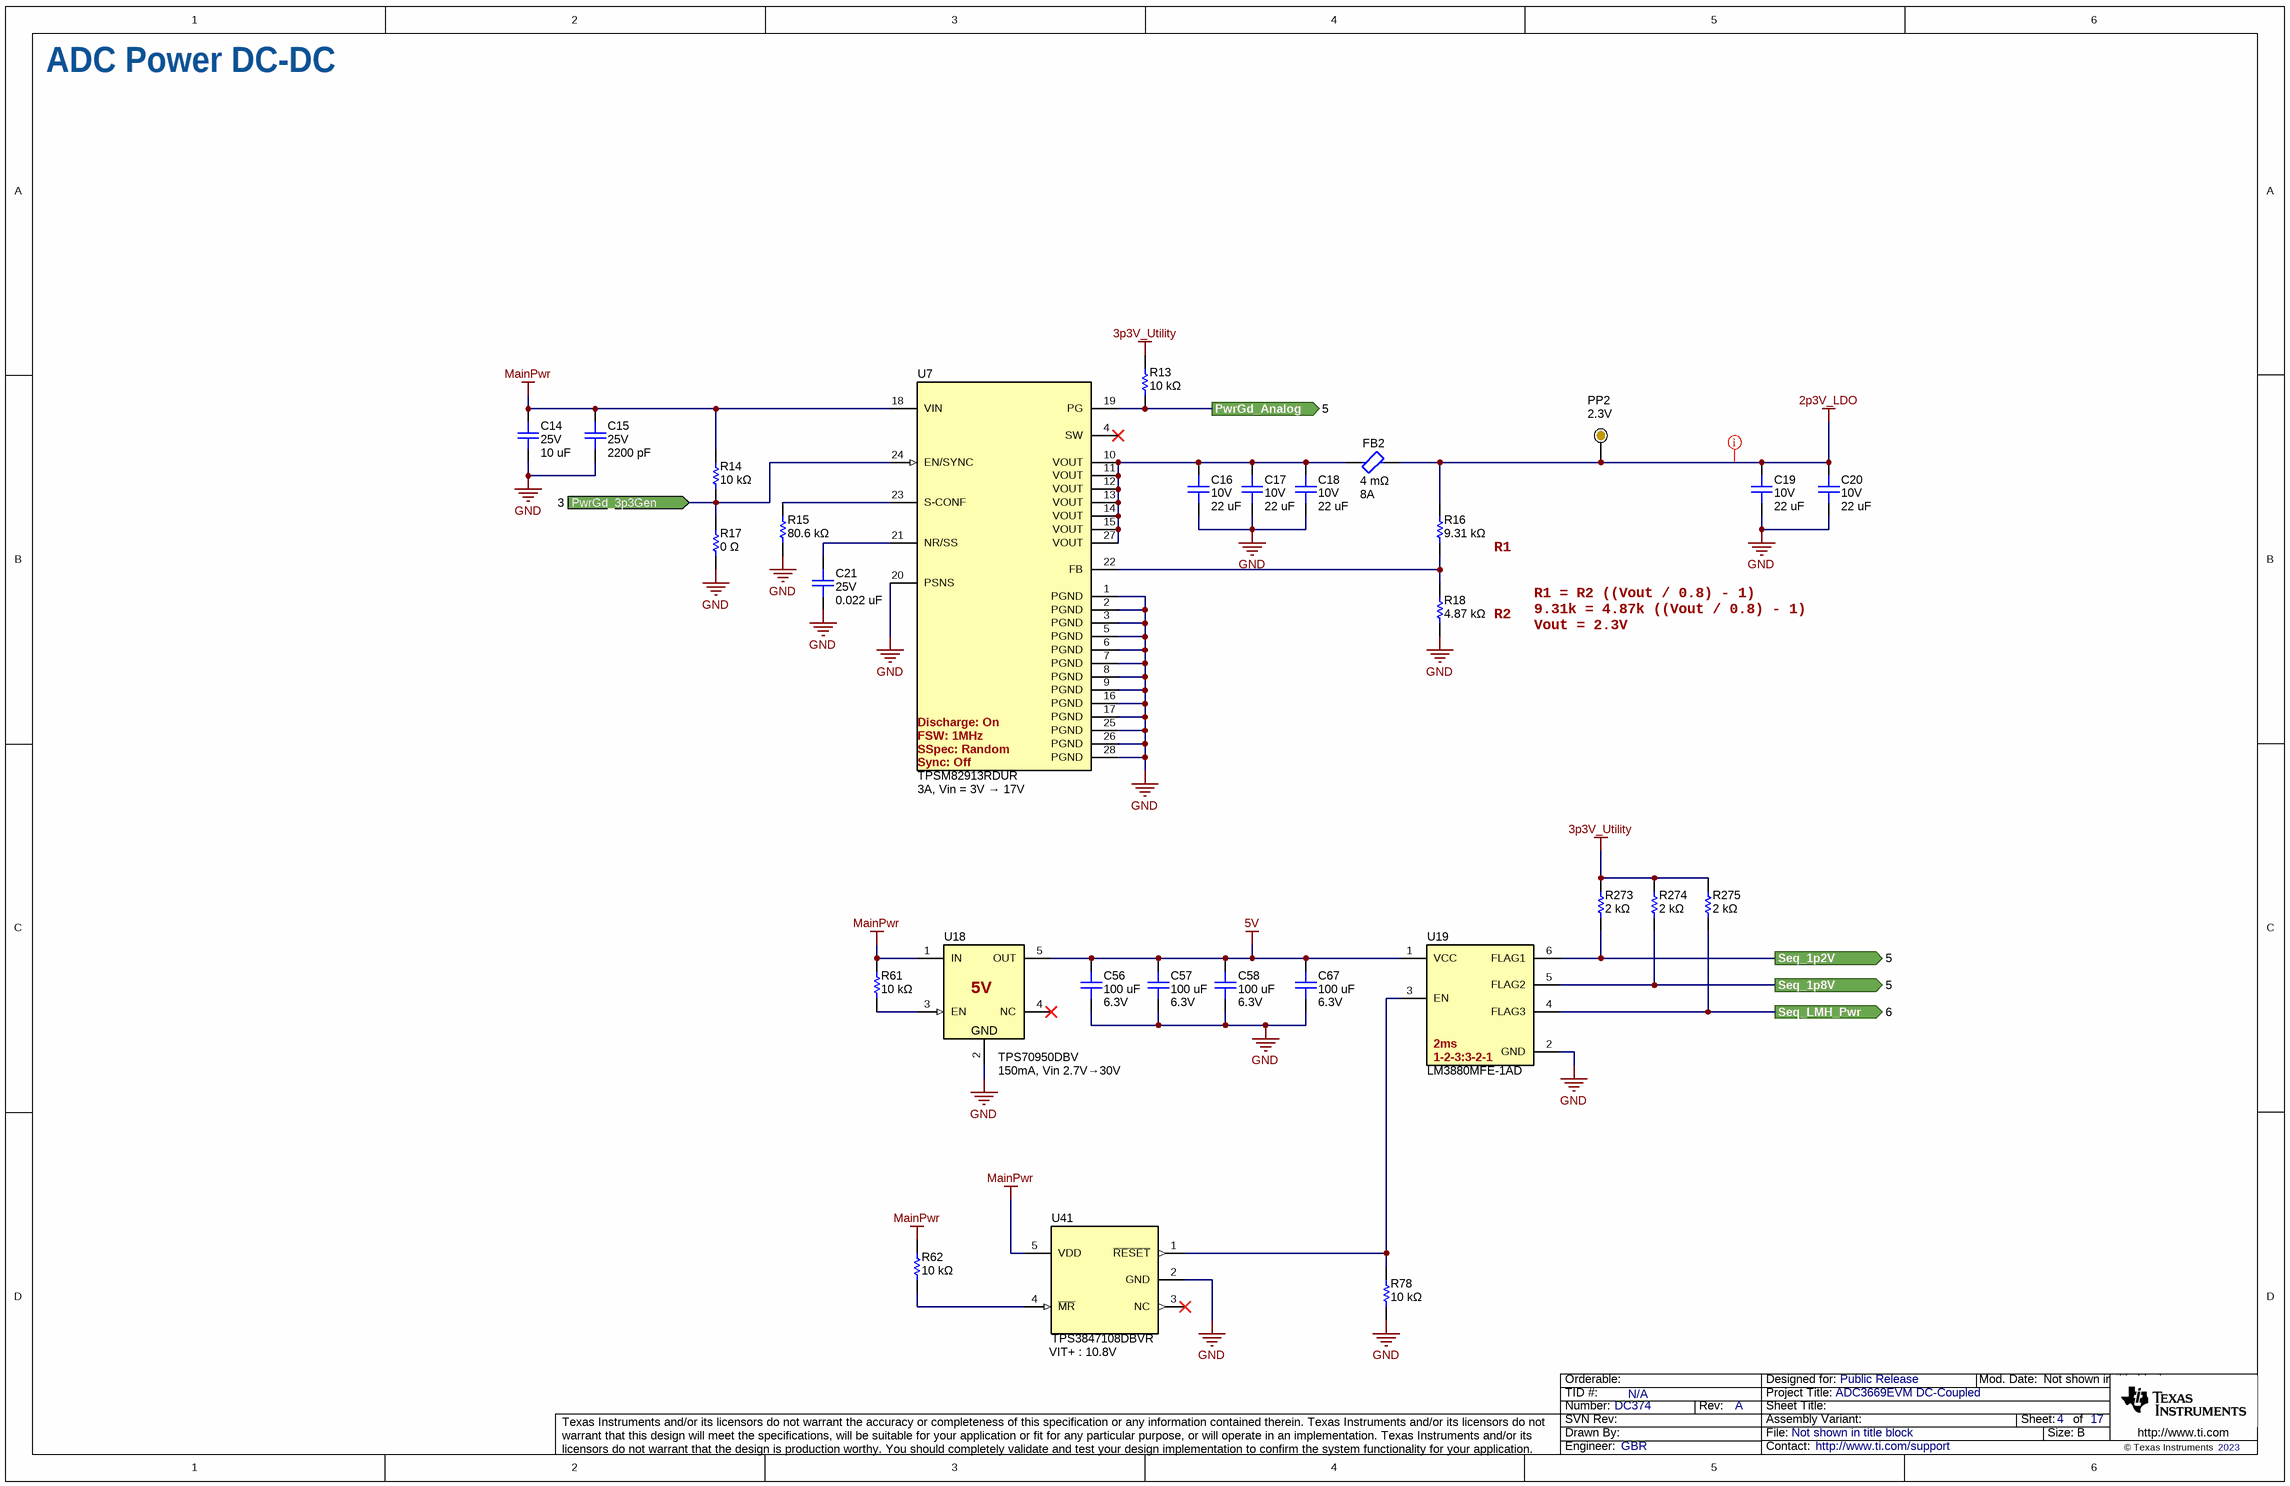
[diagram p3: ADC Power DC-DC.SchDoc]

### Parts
C14  value 10 uF  Voltage - Rated: 25V  [0805L_cap]  (hidden comment: 08053D106KAT4A)
C15  value 2200 pF  Voltage - Rated: 25V  [0402L_cap]  (hidden comment: 04023C222JAT2A)
C16  value 22 uF  Voltage - Rated: 10V  [0805L_cap]  (hidden comment: 0805ZD226KAT2A)
C17  value 22 uF  Voltage - Rated: 10V  [0805L_cap]  (hidden comment: 0805ZD226KAT2A)
C18  value 22 uF  Voltage - Rated: 10V  [0805L_cap]  (hidden comment: 0805ZD226KAT2A)
C19  value 22 uF  Voltage - Rated: 10V  [0805L_cap]  (hidden comment: 0805ZD226KAT2A)
C20  value 22 uF  Voltage - Rated: 10V  [0805L_cap]  (hidden comment: 0805ZD226KAT2A)
C21  value 0.022 uF  Voltage - Rated: 25V  [0402L_cap]  (hidden comment: CGA2B2X7R1E223K050BA)
C56  value 100 uF  Voltage - Rated: 6.3V  [0805L_cap]  (hidden comment: GMC21X5R107M6R3NT)
C57  value 100 uF  Voltage - Rated: 6.3V  [0805L_cap]  (hidden comment: GMC21X5R107M6R3NT)
C58  value 100 uF  Voltage - Rated: 6.3V  [0805L_cap]  (hidden comment: GMC21X5R107M6R3NT)
C67  value 100 uF  Voltage - Rated: 6.3V  [0805L_cap]  (hidden comment: GMC21X5R107M6R3NT)
FB2  DCR: 4 mΩ  Current: 8A  [0603L]  (hidden comment: BLE18PS080SN1D)
PP2  Text1: 2.3V  [ProbePoint_TH_40mil]  (hidden comment: Probe Point)  (no BOM)
R13  value 10 kΩ  [0402L]  (hidden comment: ERJ-2RKF1002X)
R14  value 10 kΩ  [0402L]  (hidden comment: ERJ-2RKF1002X)
R15  value 80.6 kΩ  [0402L]  (hidden comment: ERA-2AEB8062X)
R16  value 9.31 kΩ  [0402L]  (hidden comment: ERA-2AEB9311X)
R17  value 0 Ω  [0402L]  (hidden comment: ERJ-2GE0R00X)
R18  value 4.87 kΩ  [0402L]  (hidden comment: ERA-2AEB4871X)
R61  value 10 kΩ  [0402L]  (hidden comment: ERJ-2RKF1002X)
R62  value 10 kΩ  [0402L]  (hidden comment: ERJ-2RKF1002X)
R78  value 10 kΩ  [0402L]  (hidden comment: ERJ-2RKF1002X)
R273  value 2 kΩ  [0402L]  (hidden comment: ERA-2AEB202X)
R274  value 2 kΩ  [0402L]  (hidden comment: ERA-2AEB202X)
R275  value 2 kΩ  [0402L]  (hidden comment: ERA-2AEB202X)
U7  TPSM82913RDUR  Discharge: On  FSW: 1MHz  SSpec: Random  Sync: Off  Text1: 3A, Vin = 3V → 17V  [RDU0028A]
U18  TPS70950DBV  Text1: 150mA, Vin 2.7V→30V  [DBV0005A]
U19  LM3880MFE-1AD  Text1: 2ms  Seqeuence: 1-2-3:3-2-1  [DBV0006A]
U41  TPS3847108DBVR  Text1: VIT+ : 10.8V  [DBV0005A]

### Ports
PwrGd_3p3Gen (in, see 3), PwrGd_Analog (out, see 5), Seq_1p2V (out, see 5), Seq_1p8V (out, see 5), Seq_LMH_Pwr (out, see 6)

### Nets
2p3V_LDO: C19.2 C20.2 FB2.2 PP2.1 R16.2
3p3V_Utility: R13.2 R273.2 R274.2 R275.2
5V: C56.2 C57.2 C58.2 C67.2 U18.5(OUT) U19.1(VCC)
GND: C14.1 C15.1 C16.1 C17.1 C18.1 C19.1 C20.1 C21.1 C56.1 C57.1 C58.1 C67.1 R15.1 R17.1 R18.1 R78.1 U7.1(PGND) U7.2(PGND) U7.3(PGND) U7.5(PGND) U7.6(PGND) U7.7(PGND) U7.8(PGND) U7.9(PGND) U7.16(PGND) U7.17(PGND) U7.20(PSNS) U7.25(PGND) U7.26(PGND) U7.28(PGND) U18.2(GND) U19.2(GND) U41.2(GND)
MainPwr: C14.2 C15.2 R14.2 R61.2 R62.2 U7.18(VIN) U18.1(IN) U41.5(VDD)
PwrGd_3p3Gen: R14.1 R17.2 U7.24(EN/SYNC) ; port PwrGd_3p3Gen
PwrGd_Analog: R13.1 U7.19(PG) ; port PwrGd_Analog
Seq_1p2V: R273.1 U19.6(FLAG1) ; port Seq_1p2V
Seq_1p8V: R274.1 U19.5(FLAG2) ; port Seq_1p8V
Seq_LMH_Pwr: R275.1 U19.4(FLAG3) ; port Seq_LMH_Pwr
NetC16_2: C16.2 C17.2 C18.2 FB2.1 U7.10(VOUT) U7.11(VOUT) U7.12(VOUT) U7.13(VOUT) U7.14(VOUT) U7.15(VOUT) U7.27(VOUT)
NetC21_2: C21.2 U7.21(NR/SS)
NetR15_2: R15.2 U7.23(S-CONF)
NetR16_1: R16.1 R18.2 U7.22(FB)
NetR61_1: R61.1 U18.3(EN)
NetR62_1: R62.1 U41.4(~{MR})
NetR78_2: R78.2 U19.3(EN) U41.1(~{RESET})

Not connected (* = marked no-connect by the designer): U7 4(SW)*; U18 4(NC)*; U41 3(NC)*

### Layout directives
net class Power; net class ADC_Power: 2p3V_LDO

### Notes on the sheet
- ADC Power DC-DC
- R1
- R2
- R1 = R2 ((Vout / 0.8) - 1)
  9.31k = 4.87k ((Vout / 0.8) - 1)
  Vout = 2.3V
- (near U18) 5V

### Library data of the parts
C14 = capcc03515: as C7 on sheet EVM Power
C15 = capcc04225: CAP CER 2200PF 25V X7R 0402; Manufacturer: KYOCERA AVX; CompType: Capacitor Ceramic; Tolerance: ±5%; SizeX_mm: 1; SizeY_mm: 0.5; SizeZ_mm: 0.56
C16-C20 = capcc03698: CAP CER 22UF 10V X5R 0805; Manufacturer: KYOCERA AVX; CompType: Capacitor Ceramic; Tolerance: ±10%; SizeX_mm: 2.01; SizeY_mm: 1.25; SizeZ_mm: 1.52
C21 = capcc05923: CAP CER 0.022UF 25V X7R 0402; Manufacturer: TDK Corporation; CompType: Capacitor Ceramic; Tolerance: ±10%; SizeX_mm: 1; SizeY_mm: 0.5; SizeZ_mm: 0.55
C56-C58 C67 = capcc06830: CAP CER 100UF 6.3V X5R 0805; Manufacturer: CAL-CHIP ELECTRONICS, INC.; CompType: Capacitor Ceramic; Tolerance: ±20%; SizeX_mm: 2; SizeY_mm: 1.25
FB2 = dcp00004: as FB1 on sheet EVM Power
PP2 = cmp00025: Probe Point that can be used in lue of a test point
R13 R14 R61 R62 R78 = RSMD040200314: as R6 on sheet EVM Power
R15 = RSMD040203749: RES SMD 80.6KOHM 0.1% 1/16W 0402; Manufacturer: Panasonic Electronic Components; CompType: Resistor SMD; Power (Watts): 0.063W, 1/16W; Temperature Coefficient: ±25ppm/°C; SizeX_mm: 1; SizeY_mm: 0.5; SizeZ_mm: 0.4
R16 = RSMD040203923: RES SMD 9.31KOHM 0.1% 1/16W 0402; Manufacturer: Panasonic Electronic Components; CompType: Resistor SMD; Power (Watts): 0.063W, 1/16W; Temperature Coefficient: ±25ppm/°C; SizeX_mm: 1; SizeY_mm: 0.5; SizeZ_mm: 0.4
R17 = RSMD040200001: RES SMD 0 OHM JUMPER 1/10W 0402; Manufacturer: Panasonic Electronic Components; CompType: Resistor SMD; Power (Watts): 0.1W, 1/10W; SizeX_mm: 1; SizeY_mm: 0.5; SizeZ_mm: 0.4
R18 = RSMD040202615: RES SMD 4.87KOHM 0.1% 1/16W 0402; Manufacturer: Panasonic Electronic Components; CompType: Resistor SMD; Power (Watts): 0.063W, 1/16W; Temperature Coefficient: ±25ppm/°C; SizeX_mm: 1; SizeY_mm: 0.5; SizeZ_mm: 0.4
R273-R275 = RSMD040201162: RES SMD 2K OHM 0.1% 1/16W 0402; Manufacturer: Panasonic Electronic Components; CompType: Resistor SMD; Power (Watts): 0.063W, 1/16W; Temperature Coefficient: ±25ppm/°C; SizeX_mm: 1; SizeY_mm: 0.5; SizeZ_mm: 0.4
U7 = TPSM82913RDUR: 3-V to 17-V, 3-A Low-Noise and Low-Ripple Buck Power Module with Integrated Ferrite Bead Filter Compensation; Manufacturer: Texas Instruments; Switching Frequency: 1/2.2MHz; Max Duty Cycle: 100%; Output Voltage: 0.8-5.5V; Standoff Height: 0mm; CompType: Switcher; Number Of Outputs: 1; Max Supply Voltage: 17V; AEC Category: Q200; TJmax_C: +125°C; Nominal Supply Current: 5mA; Output Type: AdjustableProgrammable; Min Supply Voltage: 3V; AEC Qualified: No; UniqueID: cmp00201
U18 = TPS70950DBV: 150-mA, 30-V, ultra-low-IQ, low-dropout voltage regulator with reverse current protection and enable; Manufacturer: Texas Instruments; CompType: LDO
U19 = LM3880MFE-1AD: 3 Rail Simple Power Sequencer with Fixed Time Delay; Manufacturer: Texas Instruments
U41 = TPS3847108DBVR: 380-nA voltage monitor for 12-V rails; Manufacturer: Texas Instruments; Alt PartNumber: TPS3847108DBVT; CompType: Voltage Detector

## Sheet ADC Power.SchDoc: ADC Power
size 431 x 279 mm; Date: Not shown in title block; ApprovedBy: Not shown in title block; CheckedBy: Not shown in title block; Author: Not shown in title block; CompanyName: Not shown in title block; Engineer: Not shown in title block; Organization: Not shown in title block; Address1: Not shown in title block; Address2: Not shown in title block; Address3: Not shown in title block; Address4: Not shown in title block; DocumentNumber: 1; Revision: Use project parameter SCH_Rev; SheetNumber: 5; SheetTotal: 17; PageSetup: Record=PageOptions¦CenterHorizontal=True¦CenterVertical=True¦PrintScale=1.00¦XCorrection=1.00¦YCorrection=1.00¦PrintKind=0¦BorderSize=5000000¦LeftOffset=0¦BottomOffset=0¦Orientation=2¦PaperLength=1000¦PaperWidth=1000¦Scale=100¦PaperSource=15¦PrintQuality=600¦MediaType=1¦DitherType=10¦PaperKind=Letter¦PrintScaleMode=1
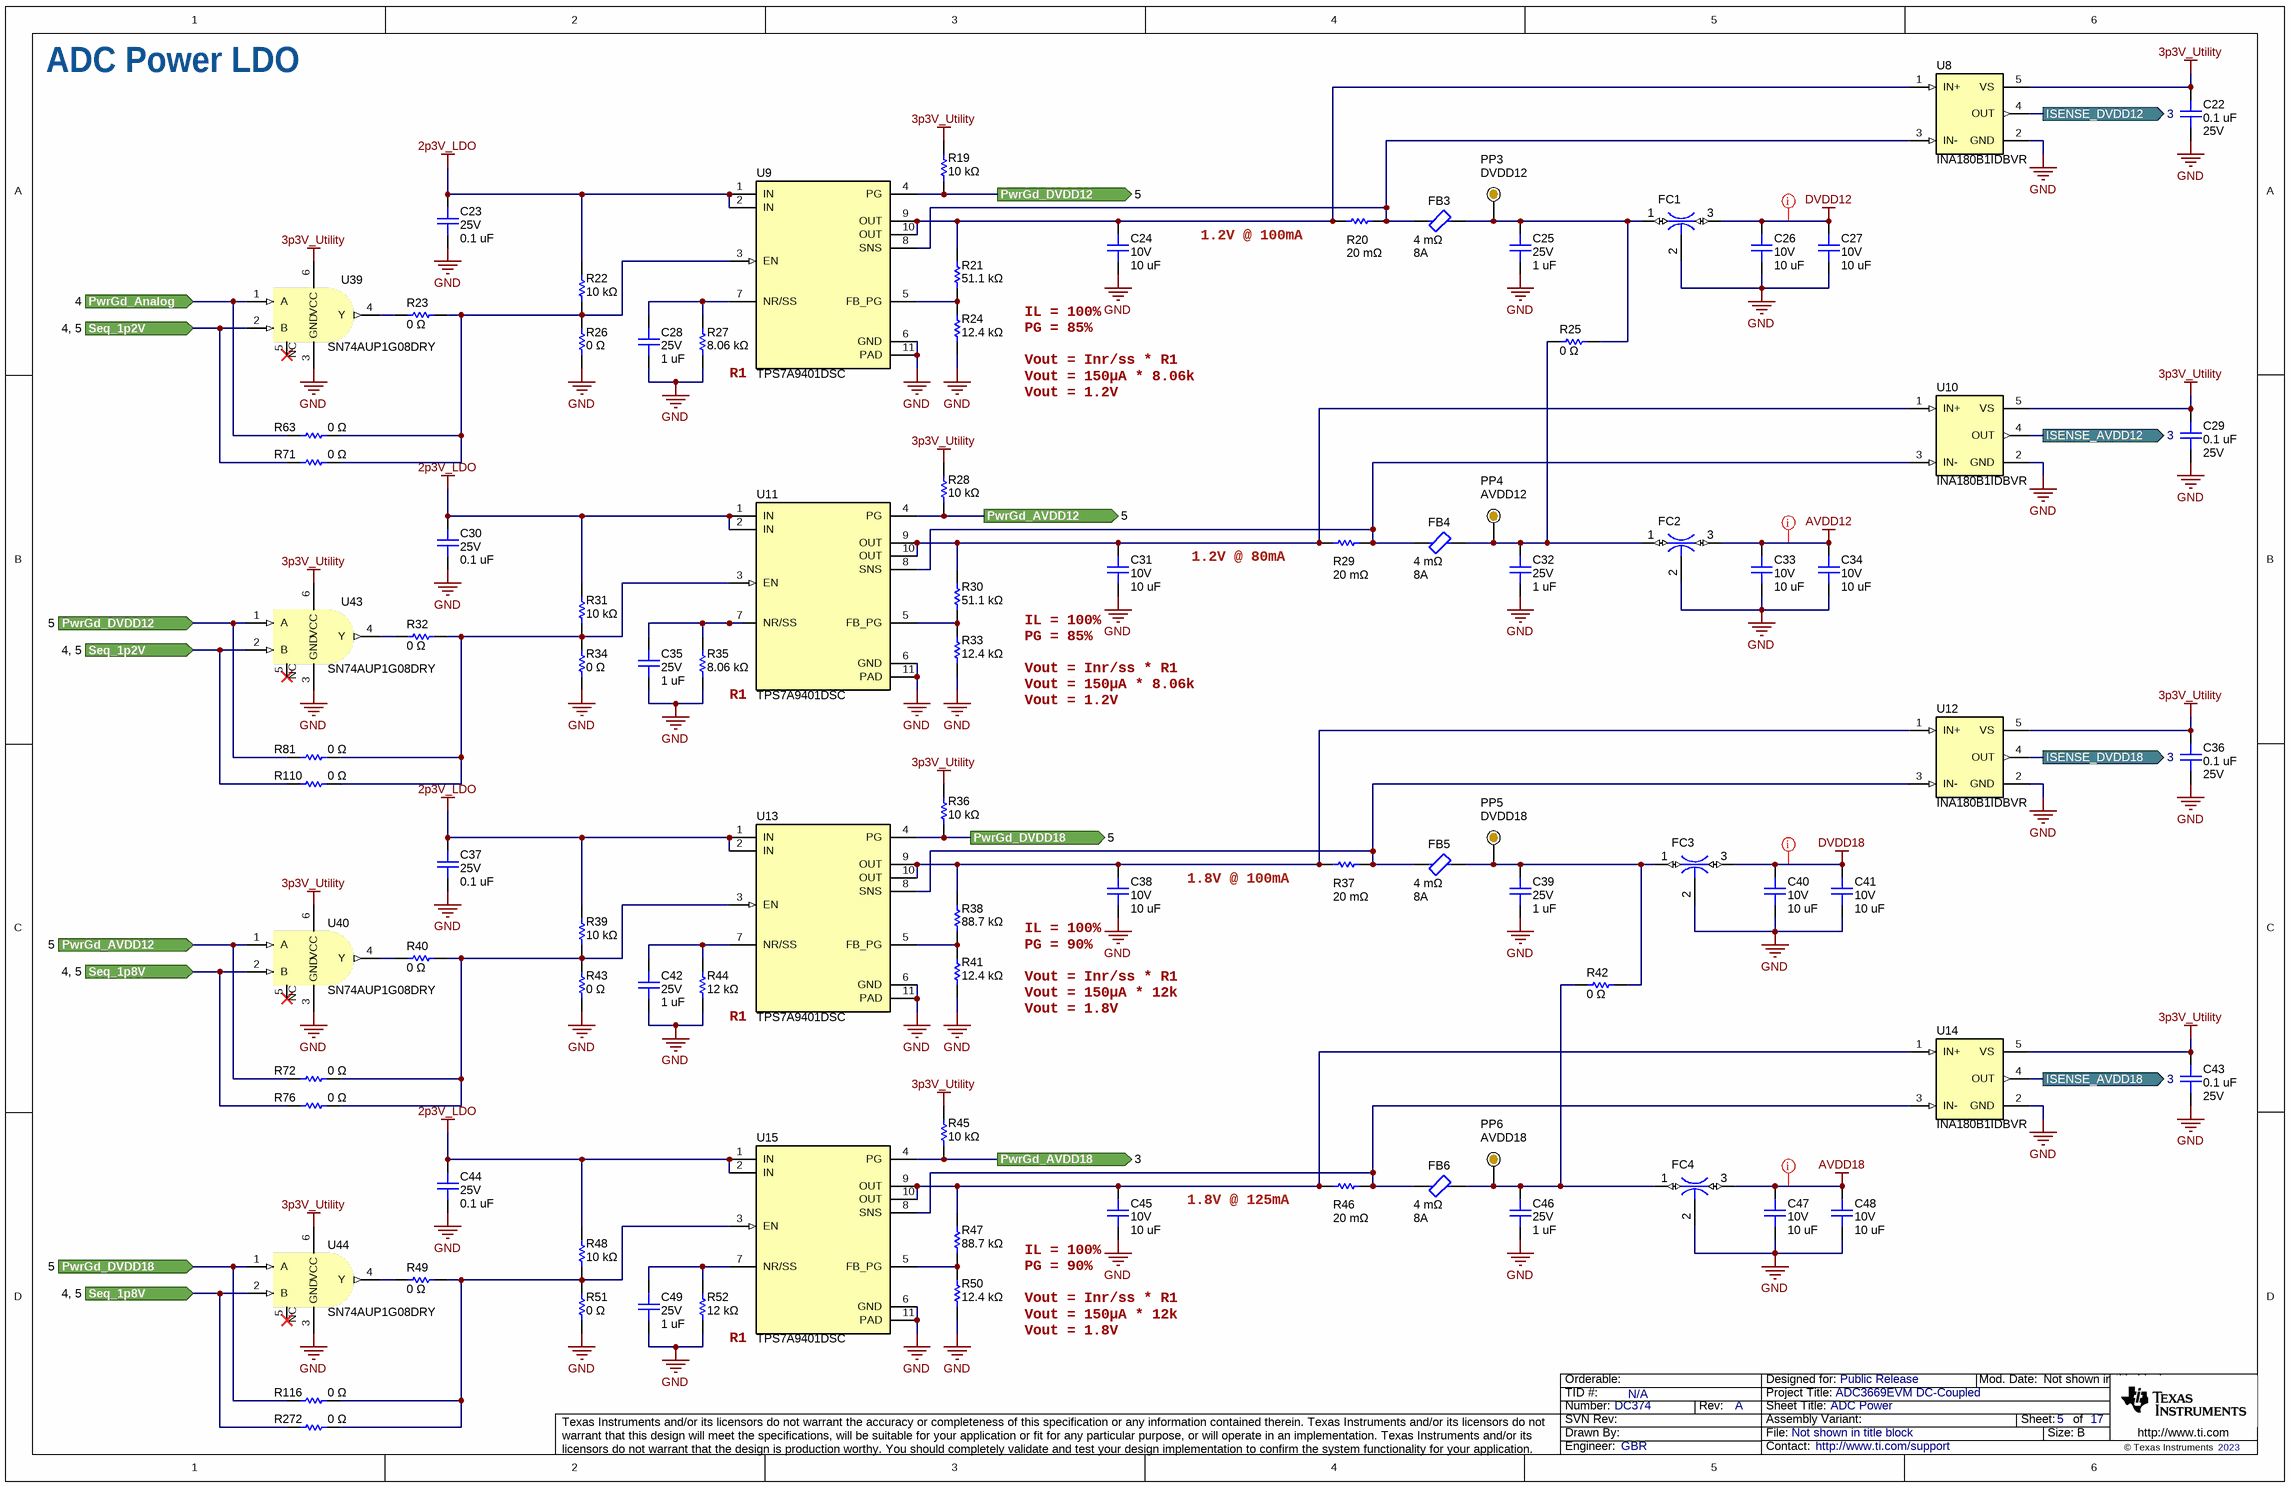
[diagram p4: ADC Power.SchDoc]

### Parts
C22  value 0.1 uF  Voltage - Rated: 25V  [0402L_cap]  (hidden comment: C1005X5R1E104K050BC)
C23  value 0.1 uF  Voltage - Rated: 25V  [0402L_cap]  (hidden comment: C1005X5R1E104K050BC)
C24  value 10 uF  Voltage - Rated: 10V  [0402L_cap]  (hidden comment: 0402ZD106MAT2A)
C25  value 1 uF  Voltage - Rated: 25V  [0402L_cap]  (hidden comment: C1005X5R1E105K050BC)
C26  value 10 uF  Voltage - Rated: 10V  [0402L_cap]  (hidden comment: 0402ZD106MAT2A)
C27  value 10 uF  Voltage - Rated: 10V  [0402L_cap]  (hidden comment: 0402ZD106MAT2A)
C28  value 1 uF  Voltage - Rated: 25V  [0402L_cap]  (hidden comment: C1005X5R1E105K050BC)
C29  value 0.1 uF  Voltage - Rated: 25V  [0402L_cap]  (hidden comment: C1005X5R1E104K050BC)
C30  value 0.1 uF  Voltage - Rated: 25V  [0402L_cap]  (hidden comment: C1005X5R1E104K050BC)
C31  value 10 uF  Voltage - Rated: 10V  [0402L_cap]  (hidden comment: 0402ZD106MAT2A)
C32  value 1 uF  Voltage - Rated: 25V  [0402L_cap]  (hidden comment: C1005X5R1E105K050BC)
C33  value 10 uF  Voltage - Rated: 10V  [0402L_cap]  (hidden comment: 0402ZD106MAT2A)
C34  value 10 uF  Voltage - Rated: 10V  [0402L_cap]  (hidden comment: 0402ZD106MAT2A)
C35  value 1 uF  Voltage - Rated: 25V  [0402L_cap]  (hidden comment: C1005X5R1E105K050BC)
C36  value 0.1 uF  Voltage - Rated: 25V  [0402L_cap]  (hidden comment: C1005X5R1E104K050BC)
C37  value 0.1 uF  Voltage - Rated: 25V  [0402L_cap]  (hidden comment: C1005X5R1E104K050BC)
C38  value 10 uF  Voltage - Rated: 10V  [0402L_cap]  (hidden comment: 0402ZD106MAT2A)
C39  value 1 uF  Voltage - Rated: 25V  [0402L_cap]  (hidden comment: C1005X5R1E105K050BC)
C40  value 10 uF  Voltage - Rated: 10V  [0402L_cap]  (hidden comment: 0402ZD106MAT2A)
C41  value 10 uF  Voltage - Rated: 10V  [0402L_cap]  (hidden comment: 0402ZD106MAT2A)
C42  value 1 uF  Voltage - Rated: 25V  [0402L_cap]  (hidden comment: C1005X5R1E105K050BC)
C43  value 0.1 uF  Voltage - Rated: 25V  [0402L_cap]  (hidden comment: C1005X5R1E104K050BC)
C44  value 0.1 uF  Voltage - Rated: 25V  [0402L_cap]  (hidden comment: C1005X5R1E104K050BC)
C45  value 10 uF  Voltage - Rated: 10V  [0402L_cap]  (hidden comment: 0402ZD106MAT2A)
C46  value 1 uF  Voltage - Rated: 25V  [0402L_cap]  (hidden comment: C1005X5R1E105K050BC)
C47  value 10 uF  Voltage - Rated: 10V  [0402L_cap]  (hidden comment: 0402ZD106MAT2A)
C48  value 10 uF  Voltage - Rated: 10V  [0402L_cap]  (hidden comment: 0402ZD106MAT2A)
C49  value 1 uF  Voltage - Rated: 25V  [0402L_cap]  (hidden comment: C1005X5R1E105K050BC)
FB3  Current: 8A  DCR: 4 mΩ  [0603L]  (hidden comment: BLE18PS080SN1D)
FB4  Current: 8A  DCR: 4 mΩ  [0603L]  (hidden comment: BLE18PS080SN1D)
FB5  Current: 8A  DCR: 4 mΩ  [0603L]  (hidden comment: BLE18PS080SN1D)
FB6  Current: 8A  DCR: 4 mΩ  [0603L]  (hidden comment: BLE18PS080SN1D)
FC1  NFM31PC276B0J3L  [NFM31PC]  (value not drawn)
FC2  NFM31PC276B0J3L  [NFM31PC]  (value not drawn)
FC3  NFM31PC276B0J3L  [NFM31PC]  (value not drawn)
FC4  NFM31PC276B0J3L  [NFM31PC]  (value not drawn)
PP3  Text1: DVDD12  [ProbePoint_TH_40mil]  (hidden comment: Probe Point)  (no BOM)
PP4  Text1: AVDD12  [ProbePoint_TH_40mil]  (hidden comment: Probe Point)  (no BOM)
PP5  Text1: DVDD18  [ProbePoint_TH_40mil]  (hidden comment: Probe Point)  (no BOM)
PP6  Text1: AVDD18  [ProbePoint_TH_40mil]  (hidden comment: Probe Point)  (no BOM)
R19  value 10 kΩ  [0402L]  (hidden comment: ERJ-2RKF1002X)
R20  value 20 mΩ  [0603L]  (hidden comment: ERJ-3BWFR020V)
R21  value 51.1 kΩ  [0402L]  (hidden comment: ERJ-2RKF5112X)
R22  value 10 kΩ  [0402L]  (hidden comment: ERJ-2RKF1002X)
R23  value 0 Ω  [0201]  (hidden comment: ERJ-1GN0R00C)
R24  value 12.4 kΩ  [0402L]  (hidden comment: ERJ-2RKF1242X)
R25  value 0 Ω  [1206L]  (hidden comment: ERJ-S080R00V)
R26  value 0 Ω  [0402L]  (hidden comment: ERJ-2GE0R00X)
R27  value 8.06 kΩ  [0402L]  (hidden comment: ERA-2APB8061X)
R28  value 10 kΩ  [0402L]  (hidden comment: ERJ-2RKF1002X)
R29  value 20 mΩ  [0603L]  (hidden comment: ERJ-3BWFR020V)
R30  value 51.1 kΩ  [0402L]  (hidden comment: ERJ-2RKF5112X)
R31  value 10 kΩ  [0402L]  (hidden comment: ERJ-2RKF1002X)
R32  value 0 Ω  [0201]  (hidden comment: ERJ-1GN0R00C)
R33  value 12.4 kΩ  [0402L]  (hidden comment: ERJ-2RKF1242X)
R34  value 0 Ω  [0402L]  (hidden comment: ERJ-2GE0R00X)
R35  value 8.06 kΩ  [0402L]  (hidden comment: ERA-2APB8061X)
R36  value 10 kΩ  [0402L]  (hidden comment: ERJ-2RKF1002X)
R37  value 20 mΩ  [0603L]  (hidden comment: ERJ-3BWFR020V)
R38  value 88.7 kΩ  [0402L]  (hidden comment: ERJ-2RKF8872X)
R39  value 10 kΩ  [0402L]  (hidden comment: ERJ-2RKF1002X)
R40  value 0 Ω  [0201]  (hidden comment: ERJ-1GN0R00C)
R41  value 12.4 kΩ  [0402L]  (hidden comment: ERJ-2RKF1242X)
R42  value 0 Ω  [1206L]  (hidden comment: ERJ-S080R00V)
R43  value 0 Ω  [0402L]  (hidden comment: ERJ-2GE0R00X)
R44  value 12 kΩ  [0402L]  (hidden comment: ERA-2ARB123X)
R45  value 10 kΩ  [0402L]  (hidden comment: ERJ-2RKF1002X)
R46  value 20 mΩ  [0603L]  (hidden comment: ERJ-3BWFR020V)
R47  value 88.7 kΩ  [0402L]  (hidden comment: ERJ-2RKF8872X)
R48  value 10 kΩ  [0402L]  (hidden comment: ERJ-2RKF1002X)
R49  value 0 Ω  [0201]  (hidden comment: ERJ-1GN0R00C)
R50  value 12.4 kΩ  [0402L]  (hidden comment: ERJ-2RKF1242X)
R51  value 0 Ω  [0402L]  (hidden comment: ERJ-2GE0R00X)
R52  value 12 kΩ  [0402L]  (hidden comment: ERA-2ARB123X)
R63  value 0 Ω  [0201]  (hidden comment: ERJ-1GN0R00C)
R71  value 0 Ω  [0201]  (hidden comment: ERJ-1GN0R00C)
R72  value 0 Ω  [0201]  (hidden comment: ERJ-1GN0R00C)
R76  value 0 Ω  [0201]  (hidden comment: ERJ-1GN0R00C)
R81  value 0 Ω  [0201]  (hidden comment: ERJ-1GN0R00C)
R110  value 0 Ω  [0201]  (hidden comment: ERJ-1GN0R00C)
R116  value 0 Ω  [0201]  (hidden comment: ERJ-1GN0R00C)
R272  value 0 Ω  [0201]  (hidden comment: ERJ-1GN0R00C)
U8  INA180B1IDBVR  [DBV0005A]
U9  TPS7A9401DSC  [DSC0010]
U10  INA180B1IDBVR  [DBV0005A]
U11  TPS7A9401DSC  [DSC0010]
U12  INA180B1IDBVR  [DBV0005A]
U13  TPS7A9401DSC  [DSC0010]
U14  INA180B1IDBVR  [DBV0005A]
U15  TPS7A9401DSC  [DSC0010]
U39  SN74AUP1G08DRY  [DRY0006A]
U40  SN74AUP1G08DRY  [DRY0006A]
U43  SN74AUP1G08DRY  [DRY0006A]
U44  SN74AUP1G08DRY  [DRY0006A]

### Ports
ISENSE_AVDD12 (out, see 3), ISENSE_AVDD18 (out, see 3), ISENSE_DVDD12 (out, see 3), ISENSE_DVDD18 (out, see 3), PwrGd_Analog (in, see 4), PwrGd_AVDD12 (in, see 5), PwrGd_AVDD12 (out, see 5), PwrGd_AVDD18 (out, see 3), PwrGd_DVDD12 (in, see 5), PwrGd_DVDD12 (out, see 5), PwrGd_DVDD18 (in, see 5), PwrGd_DVDD18 (out, see 5), Seq_1p2V (in, see 4, 5), Seq_1p8V (in, see 4, 5)

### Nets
2p3V_LDO: C23.2 C30.2 C37.2 C44.2 R22.2 R31.2 R39.2 R48.2 U9.1(IN) U9.2(IN) U11.1(IN) U11.2(IN) U13.1(IN) U13.2(IN) U15.1(IN) U15.2(IN)
3p3V_Utility: C22.2 C29.2 C36.2 C43.2 R19.2 R28.2 R36.2 R45.2 U8.5(VS) U10.5(VS) U12.5(VS) U14.5(VS) U39.6(VCC) U40.6(VCC) U43.6(VCC) U44.6(VCC)
AVDD12: C33.2 C34.2 FC2.3
AVDD18: C47.2 C48.2 FC4.3
DVDD12: C26.2 C27.2 FC1.3
DVDD18: C40.2 C41.2 FC3.3
GND: C22.1 C23.1 C24.1 C25.1 C26.1 C27.1 C28.1 C29.1 C30.1 C31.1 C32.1 C33.1 C34.1 C35.1 C36.1 C37.1 C38.1 C39.1 C40.1 C41.1 C42.1 C43.1 C44.1 C45.1 C46.1 C47.1 C48.1 C49.1 FC1.2 FC2.2 FC3.2 FC4.2 R24.1 R26.1 R27.1 R33.1 R34.1 R35.1 R41.1 R43.1 R44.1 R50.1 R51.1 R52.1 U8.2(GND) U9.6(GND) U9.11(PAD) U10.2(GND) U11.6(GND) U11.11(PAD) U12.2(GND) U13.6(GND) U13.11(PAD) U14.2(GND) U15.6(GND) U15.11(PAD) U39.3(GND) U40.3(GND) U43.3(GND) U44.3(GND)
ISENSE_AVDD12: U10.4(OUT) ; port ISENSE_AVDD12
ISENSE_AVDD18: U14.4(OUT) ; port ISENSE_AVDD18
ISENSE_DVDD12: U8.4(OUT) ; port ISENSE_DVDD12
ISENSE_DVDD18: U12.4(OUT) ; port ISENSE_DVDD18
PwrGd_Analog: R63.1 U39.1(A) ; port PwrGd_Analog
PwrGd_AVDD12: R28.1 R72.1 U11.4(PG) U40.1(A) ; port PwrGd_AVDD12
PwrGd_AVDD18: R45.1 U15.4(PG) ; port PwrGd_AVDD18
PwrGd_DVDD12: R19.1 R81.1 U9.4(PG) U43.1(A) ; port PwrGd_DVDD12
PwrGd_DVDD18: R36.1 R116.1 U13.4(PG) U44.1(A) ; port PwrGd_DVDD18
Seq_1p2V: R71.1 R110.1 U39.2(B) U43.2(B) ; port Seq_1p2V
Seq_1p8V: R76.1 R272.1 U40.2(B) U44.2(B) ; port Seq_1p8V
NetC24_2: C24.2 R20.2 R21.2 U8.1(IN+) U9.9(OUT) U9.10(OUT)
NetC25_2: C25.2 FB3.2 FC1.1 PP3.1 R25.2
NetC28_2: C28.2 R27.2 U9.7(NR/SS)
NetC31_2: C31.2 R29.2 R30.2 U10.1(IN+) U11.9(OUT) U11.10(OUT)
NetC32_2: C32.2 FB4.2 FC2.1 PP4.1 R25.1
NetC35_2: C35.2 R35.2 U11.7(NR/SS)
NetC38_2: C38.2 R37.2 R38.2 U12.1(IN+) U13.9(OUT) U13.10(OUT)
NetC39_2: C39.2 FB5.2 FC3.1 PP5.1 R42.2
NetC42_2: C42.2 R44.2 U13.7(NR/SS)
NetC45_2: C45.2 R46.2 R47.2 U14.1(IN+) U15.9(OUT) U15.10(OUT)
NetC46_2: C46.2 FB6.2 FC4.1 PP6.1 R42.1
NetC49_2: C49.2 R52.2 U15.7(NR/SS)
NetFB3_1: FB3.1 R20.1 U8.3(IN-) U9.8(SNS)
NetFB4_1: FB4.1 R29.1 U10.3(IN-) U11.8(SNS)
NetFB5_1: FB5.1 R37.1 U12.3(IN-) U13.8(SNS)
NetFB6_1: FB6.1 R46.1 U14.3(IN-) U15.8(SNS)
NetR21_1: R21.1 R24.2 U9.5(FB_PG)
NetR22_1: R22.1 R23.1 R26.2 R63.2 R71.2 U9.3(EN)
NetR23_2: R23.2 U39.4(Y)
NetR30_1: R30.1 R33.2 U11.5(FB_PG)
NetR31_1: R31.1 R32.1 R34.2 R81.2 R110.2 U11.3(EN)
NetR32_2: R32.2 U43.4(Y)
NetR38_1: R38.1 R41.2 U13.5(FB_PG)
NetR39_1: R39.1 R40.1 R43.2 R72.2 R76.2 U13.3(EN)
NetR40_2: R40.2 U40.4(Y)
NetR47_1: R47.1 R50.2 U15.5(FB_PG)
NetR48_1: R48.1 R49.1 R51.2 R116.2 R272.2 U15.3(EN)
NetR49_2: R49.2 U44.4(Y)

Not connected (* = marked no-connect by the designer): U39 5(NC)*; U40 5(NC)*; U43 5(NC)*; U44 5(NC)*

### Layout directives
net class Power; net class ADC_Power: AVDD12, AVDD18, DVDD12, DVDD18

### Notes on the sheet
- ADC Power LDO
- (near R20) 1.2V @ 100mA
- (near U9) R1
- (near C24) IL = 100%
  PG = 85%
  Vout = Inr/ss * R1
  Vout = 150μA * 8.06k
  Vout = 1.2V
- 1.2V @ 80mA
- (near U11) R1
- (near C31) IL = 100%
  PG = 85%
  Vout = Inr/ss * R1
  Vout = 150μA * 8.06k
  Vout = 1.2V
- 1.8V @ 100mA
- (near U13) R1
- (near C38) IL = 100%
  PG = 90%
  Vout = Inr/ss * R1
  Vout = 150μA * 12k
  Vout = 1.8V
- 1.8V @ 125mA
- (near U15) R1
- (near C45) IL = 100%
  PG = 90%
  Vout = Inr/ss * R1
  Vout = 150μA * 12k
  Vout = 1.8V

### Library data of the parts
C22 C23 C29 C30 C36 C37 C43 C44 = capcc01263: as C5 on sheet EVM Power
C24 C26 C27 C31 C33 C34 C38 C40 C41 C45 C47 C48 = capcc09406: as C1 on sheet EVM Power
C25 C28 C32 C35 C39 C42 C46 C49 = capcc02750: CAP CER 1UF 25V X5R 0402; Manufacturer: TDK Corporation; CompType: Capacitor Ceramic; Tolerance: ±10%; SizeX_mm: 1; SizeY_mm: 0.5; SizeZ_mm: 0.55
FB3-FB6 = dcp00004: as FB1 on sheet EVM Power
FC1-FC4 = dcp00001: Feed through capactior 27uF; Manufacturer: Murata; CompType: Feed Thru Cap; Tolerance: ±20%; Voltage - Rated: 6.3V; SizeX_mm: 3.2; SizeY_mm: 1.6; SizeZ_mm: 1.5; Current: 6A; DCR: 5 mΩ
PP3-PP6 = cmp00025: as PP2 on sheet ADC Power DC-DC
R19 R22 R28 R31 R36 R39 R45 R48 = RSMD040200314: as R6 on sheet EVM Power
R20 R29 R37 R46 = RSMD060312209: RES 0.02 OHM 1% 1/3W 0603; Manufacturer: Panasonic Electronic Components; CompType: Resistor SMD; Power (Watts): 0.333W, 1/3W; Temperature Coefficient: ±250ppm/°C; SizeX_mm: 1.6; SizeY_mm: 0.8; SizeZ_mm: 0.65
R21 R30 = RSMD040203023: RES SMD 51.1K OHM 1% 1/10W 0402; Manufacturer: Panasonic Electronic Components; CompType: Resistor SMD; Power (Watts): 0.1W, 1/10W; Temperature Coefficient: ±100ppm/°C; SizeX_mm: 1; SizeY_mm: 0.5; SizeZ_mm: 0.4
R23 R32 R40 R49 R63 R71 R72 R76 R81 R110 R116 R272 = RSMD020101699: RES SMD 0 OHM JUMPER 1/20W 0201; Manufacturer: Panasonic Electronic Components; CompType: Resistor SMD; Power (Watts): 0.05W, 1/20W
R24 R33 R41 R50 = RSMD040200547: RES SMD 12.4K OHM 1% 1/10W 0402; Manufacturer: Panasonic Electronic Components; CompType: Resistor SMD; Power (Watts): 0.1W, 1/10W; Temperature Coefficient: ±100ppm/°C; SizeX_mm: 1; SizeY_mm: 0.5; SizeZ_mm: 0.4
R25 R42 = RSMD120607125: RES SMD 0 OHM JUMPER 1/4W 1206; Manufacturer: Panasonic Electronic Components; CompType: Resistor SMD; Power (Watts): 0.25W, 1/4W; SizeX_mm: 3.2; SizeY_mm: 1.6; SizeZ_mm: 0.7
R26 R34 R43 R51 = RSMD040200001: as R17 on sheet ADC Power DC-DC
R27 R35 = RSMD040203700: RES SMD 8.06KOHM 0.1% 1/16W 0402; Manufacturer: Panasonic Electronic Components; CompType: Resistor SMD; Power (Watts): 0.063W, 1/16W; Temperature Coefficient: ±15ppm/°C; SizeX_mm: 1; SizeY_mm: 0.5; SizeZ_mm: 0.4
R38 R47 = RSMD040203879: RES SMD 88.7K OHM 1% 1/10W 0402; Manufacturer: Panasonic Electronic Components; CompType: Resistor SMD; Power (Watts): 0.1W, 1/10W; Temperature Coefficient: ±100ppm/°C; SizeX_mm: 1; SizeY_mm: 0.5; SizeZ_mm: 0.4
R44 R52 = RSMD040200520: as R11 on sheet EVM Power
U8 U10 U12 U14 = INA180B1IDBVR: 26V, 350kHz current sense amplifier; Manufacturer: Texas Instruments; Alt PartNumber: INA180B1IDBVT; CompType: Current Amplifier
U9 U11 U13 U15 = cmp00169: 1-A, ultra-low noise, ultra-high PSRR, RF voltage regulator; Manufacturer: Texas Instruments; CompType: LDO; Text1: 1A, Vin 1.7V→5.7V
U39 U40 U43 U44 = cmp00518: Low-Power Single 2-Input Positive-AND Gate; PartNumber: SN74AUP1G08DRYR; Manufacturer: Texas Instruments

## Sheet LMH Power DC-DC.SchDoc
size 431 x 279 mm; Date: Not shown in title block; ApprovedBy: Not shown in title block; CheckedBy: Not shown in title block; Author: Not shown in title block; CompanyName: Not shown in title block; Engineer: Not shown in title block; Organization: Not shown in title block; Address1: Not shown in title block; Address2: Not shown in title block; Address3: Not shown in title block; Address4: Not shown in title block; DocumentNumber: 1; Revision: Use project parameter SCH_Rev; SheetNumber: 6; SheetTotal: 17; PageSetup: Record=PageOptions¦CenterHorizontal=True¦CenterVertical=True¦PrintScale=1.00¦XCorrection=1.00¦YCorrection=1.00¦PrintKind=0¦BorderSize=5000000¦LeftOffset=0¦BottomOffset=0¦Orientation=2¦PaperLength=1000¦PaperWidth=1000¦Scale=100¦PaperSource=15¦PrintQuality=600¦MediaType=1¦DitherType=10¦PaperKind=Letter¦PrintScaleMode=1
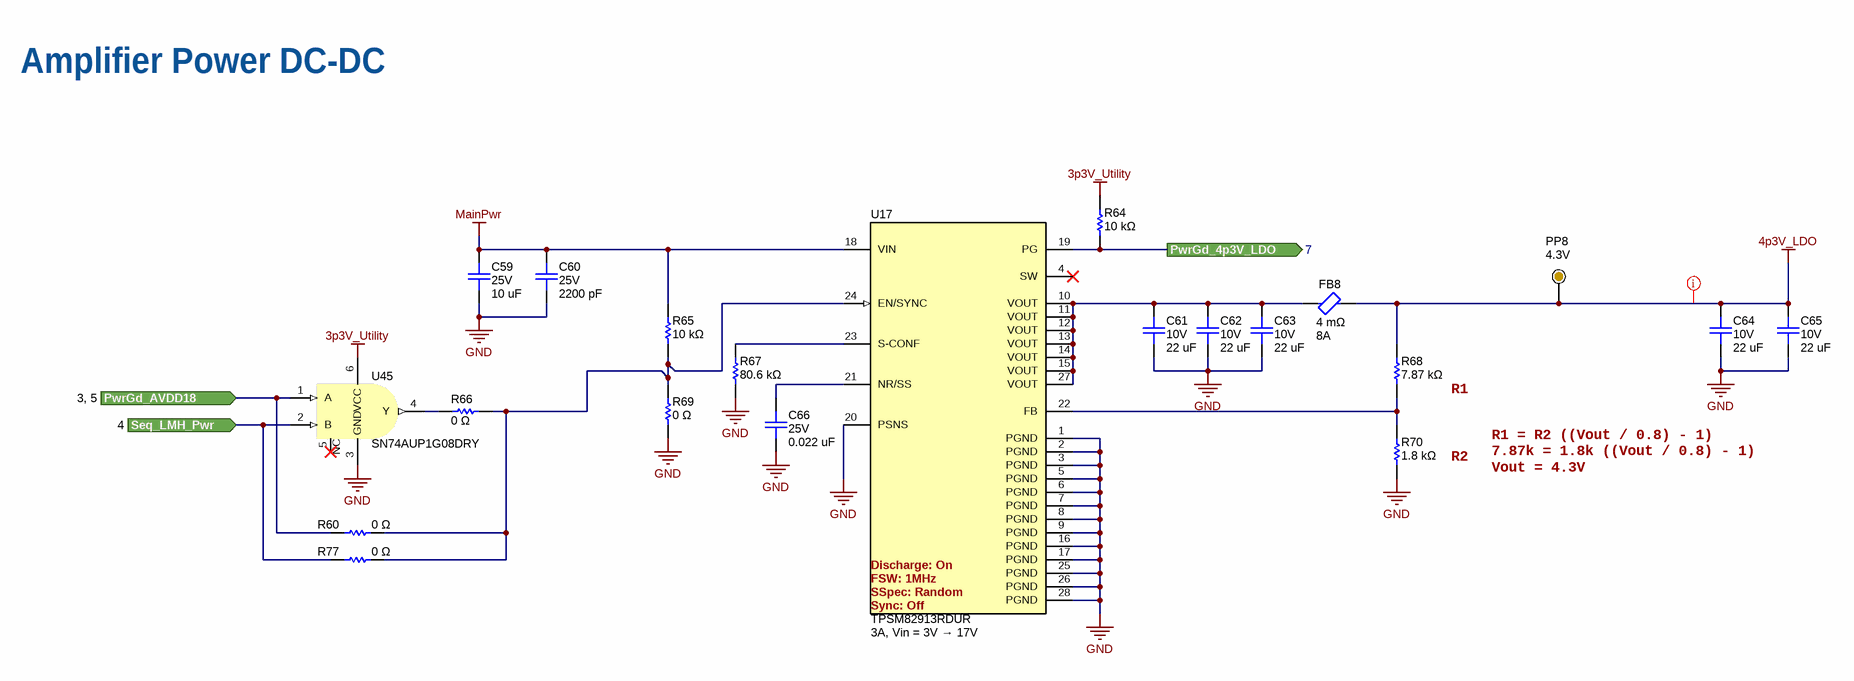
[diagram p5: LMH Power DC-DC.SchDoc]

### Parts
C59  value 10 uF  Voltage - Rated: 25V  [0805L_cap]  (hidden comment: 08053D106KAT4A)
C60  value 2200 pF  Voltage - Rated: 25V  [0402L_cap]  (hidden comment: 04023C222JAT2A)
C61  value 22 uF  Voltage - Rated: 10V  [0805L_cap]  (hidden comment: 0805ZD226KAT2A)
C62  value 22 uF  Voltage - Rated: 10V  [0805L_cap]  (hidden comment: 0805ZD226KAT2A)
C63  value 22 uF  Voltage - Rated: 10V  [0805L_cap]  (hidden comment: 0805ZD226KAT2A)
C64  value 22 uF  Voltage - Rated: 10V  [0805L_cap]  (hidden comment: 0805ZD226KAT2A)
C65  value 22 uF  Voltage - Rated: 10V  [0805L_cap]  (hidden comment: 0805ZD226KAT2A)
C66  value 0.022 uF  Voltage - Rated: 25V  [0402L_cap]  (hidden comment: CGA2B2X7R1E223K050BA)
FB8  DCR: 4 mΩ  Current: 8A  [0603L]  (hidden comment: BLE18PS080SN1D)
PP8  Text1: 4.3V  [ProbePoint_TH_40mil]  (hidden comment: Probe Point)  (no BOM)
R60  value 0 Ω  [0201]  (hidden comment: ERJ-1GN0R00C)
R64  value 10 kΩ  [0402L]  (hidden comment: ERJ-2RKF1002X)
R65  value 10 kΩ  [0402L]  (hidden comment: ERJ-2RKF1002X)
R66  value 0 Ω  [0402L]  (hidden comment: ERJ-U020R00X)
R67  value 80.6 kΩ  [0402L]  (hidden comment: ERA-2AEB8062X)
R68  value 7.87 kΩ  [0402L]  (hidden comment: ERA-2AEB7871X)
R69  value 0 Ω  [0402L]  (hidden comment: ERJ-2GE0R00X)
R70  value 1.8 kΩ  [0402L]  (hidden comment: ERA-2ARB182X)
R77  value 0 Ω  [0201]  (hidden comment: ERJ-1GN0R00C)
U17  TPSM82913RDUR  Discharge: On  FSW: 1MHz  SSpec: Random  Sync: Off  Text1: 3A, Vin = 3V → 17V  [RDU0028A]
U45  SN74AUP1G08DRY  [DRY0006A]

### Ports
PwrGd_4p3V_LDO (out, see 7), PwrGd_AVDD18 (in, see 3, 5), Seq_LMH_Pwr (in, see 4)

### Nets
3p3V_Utility: R64.2 U45.6(VCC)
4p3V_LDO: C64.2 C65.2 FB8.2 PP8.1 R68.2
GND: C59.1 C60.1 C61.1 C62.1 C63.1 C64.1 C65.1 C66.1 R67.1 R69.1 R70.1 U17.1(PGND) U17.2(PGND) U17.3(PGND) U17.5(PGND) U17.6(PGND) U17.7(PGND) U17.8(PGND) U17.9(PGND) U17.16(PGND) U17.17(PGND) U17.20(PSNS) U17.25(PGND) U17.26(PGND) U17.28(PGND) U45.3(GND)
MainPwr: C59.2 C60.2 R65.2 U17.18(VIN)
PwrGd_4p3V_LDO: R64.1 U17.19(PG) ; port PwrGd_4p3V_LDO
PwrGd_AVDD18: R60.1 U45.1(A) ; port PwrGd_AVDD18
Seq_LMH_Pwr: R77.1 U45.2(B) ; port Seq_LMH_Pwr
NetC61_2: C61.2 C62.2 C63.2 FB8.1 U17.10(VOUT) U17.11(VOUT) U17.12(VOUT) U17.13(VOUT) U17.14(VOUT) U17.15(VOUT) U17.27(VOUT)
NetC66_2: C66.2 U17.21(NR/SS)
NetR60_2: R60.2 R65.1 R66.1 R69.2 R77.2 U17.24(EN/SYNC)
NetR66_2: R66.2 U45.4(Y)
NetR67_2: R67.2 U17.23(S-CONF)
NetR68_1: R68.1 R70.2 U17.22(FB)

Not connected (* = marked no-connect by the designer): U17 4(SW)*; U45 5(NC)*

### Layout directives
net class Power; net class ADC_Power: 4p3V_LDO

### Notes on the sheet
- Amplifier Power DC-DC
- R1
- R2
- R1 = R2 ((Vout / 0.8) - 1)
  7.87k = 1.8k ((Vout / 0.8) - 1)
  Vout = 4.3V

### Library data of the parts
C59 = capcc03515: as C7 on sheet EVM Power
C60 = capcc04225: as C15 on sheet ADC Power DC-DC
C61-C65 = capcc03698: as C16 on sheet ADC Power DC-DC
C66 = capcc05923: as C21 on sheet ADC Power DC-DC
FB8 = dcp00004: as FB1 on sheet EVM Power
PP8 = cmp00025: as PP2 on sheet ADC Power DC-DC
R60 R77 = RSMD020101699: as R23 on sheet ADC Power
R64 R65 = RSMD040200314: as R6 on sheet EVM Power
R66 = RSMD040200004: RES 0 OHM JUMPER 0402 SMD; Manufacturer: Panasonic Electronic Components; CompType: Resistor SMD; Power (Watts): 0.1W, 1/10W; Temperature Coefficient: -100/ +600ppm/°C; SizeX_mm: 1; SizeY_mm: 0.5; SizeZ_mm: 0.4
R67 = RSMD040203749: as R15 on sheet ADC Power DC-DC
R68 = RSMD040203577: RES SMD 7.87KOHM 0.1% 1/16W 0402; Manufacturer: Panasonic Electronic Components; CompType: Resistor SMD; Power (Watts): 0.063W, 1/16W; Temperature Coefficient: ±25ppm/°C; SizeX_mm: 1; SizeY_mm: 0.5; SizeZ_mm: 0.4
R69 = RSMD040200001: as R17 on sheet ADC Power DC-DC
R70 = RSMD040200273: RES SMD 1.8K OHM 0.1% 1/16W 0402; Manufacturer: Panasonic Electronic Components; CompType: Resistor SMD; Power (Watts): 0.063W, 1/16W; Temperature Coefficient: ±10ppm/°C; SizeX_mm: 1; SizeY_mm: 0.5; SizeZ_mm: 0.4
U17 = TPSM82913RDUR: as U7 on sheet ADC Power DC-DC
U45 = cmp00518: as U39 on sheet ADC Power

## Sheet LMH Power LDO.SchDoc
size 431 x 279 mm; Date: Not shown in title block; ApprovedBy: Not shown in title block; CheckedBy: Not shown in title block; Author: Not shown in title block; CompanyName: Not shown in title block; Engineer: Not shown in title block; Organization: Not shown in title block; Address1: Not shown in title block; Address2: Not shown in title block; Address3: Not shown in title block; Address4: Not shown in title block; DocumentNumber: 1; Revision: Use project parameter SCH_Rev; SheetNumber: 7; SheetTotal: 17; PageSetup: Record=PageOptions¦CenterHorizontal=True¦CenterVertical=True¦PrintScale=1.00¦XCorrection=1.00¦YCorrection=1.00¦PrintKind=0¦BorderSize=5000000¦LeftOffset=0¦BottomOffset=0¦Orientation=2¦PaperLength=1000¦PaperWidth=1000¦Scale=100¦PaperSource=15¦PrintQuality=600¦MediaType=1¦DitherType=10¦PaperKind=Letter¦PrintScaleMode=1
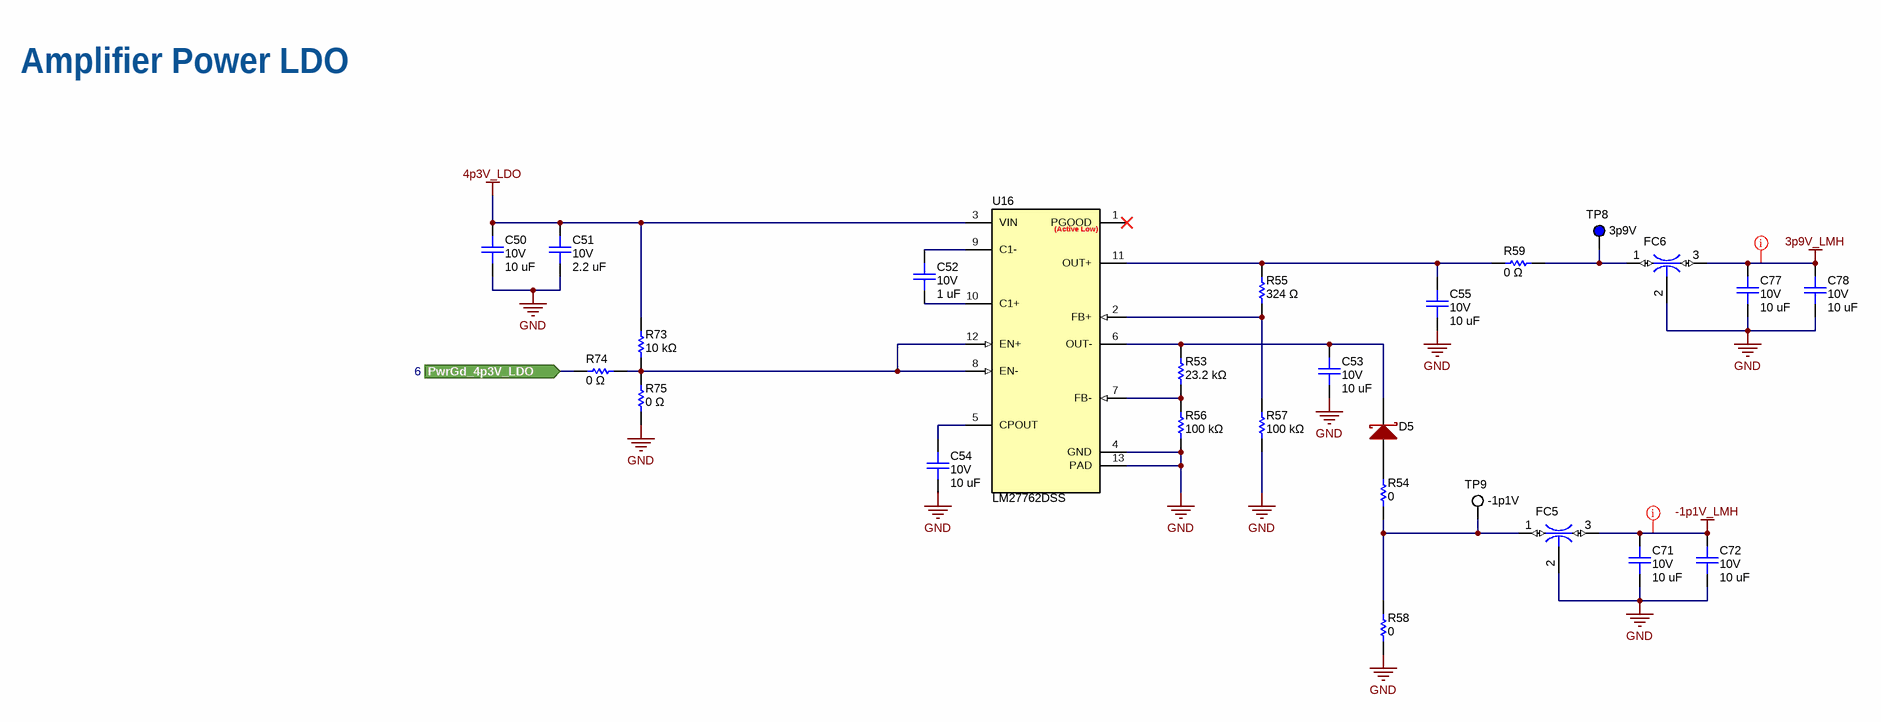
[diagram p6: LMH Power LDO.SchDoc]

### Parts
C50  value 10 uF  Voltage - Rated: 10V  [0603L_cap]  (hidden comment: 0603ZD106KAT2A)
C51  value 2.2 uF  Voltage - Rated: 10V  [0402L_cap]  (hidden comment: C1005X5R1A225K050BC)
C52  value 1 uF  Voltage - Rated: 10V  [0201_cap]  (hidden comment: GRM033R61A105ME44D)
C53  value 10 uF  Voltage - Rated: 10V  [0603L_cap]  (hidden comment: 0603ZD106KAT2A)
C54  value 10 uF  Voltage - Rated: 10V  [0603L_cap]  (hidden comment: 0603ZD106KAT2A)
C55  value 10 uF  Voltage - Rated: 10V  [0603L_cap]  (hidden comment: 0603ZD106KAT2A)
C71  value 10 uF  Voltage - Rated: 10V  [0402L_cap]  (hidden comment: 0402ZD106MAT2A)
C72  value 10 uF  Voltage - Rated: 10V  [0402L_cap]  (hidden comment: 0402ZD106MAT2A)
C77  value 10 uF  Voltage - Rated: 10V  [0402L_cap]  (hidden comment: 0402ZD106MAT2A)
C78  value 10 uF  Voltage - Rated: 10V  [0402L_cap]  (hidden comment: 0402ZD106MAT2A)
D5  RBR3LAM40ATR  [SOD-128]  (value not drawn)
FC5  NFM31PC276B0J3L  [NFM31PC]  (value not drawn)
FC6  NFM31PC276B0J3L  [NFM31PC]  (value not drawn)
R53  value 23.2 kΩ  [0402L]  (hidden comment: ERA-2AEB2322X)
R54  ValueDisplayed: 0  [2010]  (hidden comment: CRCW20100000Z0EF)
R55  value 324 Ω  [0402L]  (hidden comment: ERA-2AEB3240X)
R56  value 100 kΩ  [0402L]  (hidden comment: ERA-2AEB104X)
R57  value 100 kΩ  [0402L]  (hidden comment: ERA-2AEB104X)
R58  ValueDisplayed: 0  [2010]  (hidden comment: CRCW20100000Z0EF)
R59  value 0 Ω  [0805L]  (hidden comment: ERJ-6GEY0R00V)
R73  value 10 kΩ  [0402L]  (hidden comment: ERJ-2RKF1002X)
R74  value 0 Ω  [0402L]  (hidden comment: ERJ-2GE0R00X)
R75  value 0 Ω  [0402L]  (hidden comment: ERJ-2GE0R00X)
TP8  Text1: 3p9V  [Keystone5127]  (hidden comment: 5127)
TP9  Text1: -1p1V  [Keystone5012]  (hidden comment: 5012)
U16  LM27762DSS  [DSS0012B]

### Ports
PwrGd_4p3V_LDO (in, see 6)

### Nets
3p9V_LMH: C77.2 C78.2 FC6.3
4p3V_LDO: C50.2 C51.2 R73.2 U16.3(VIN)
-1p1V_LMH: C71.2 C72.2 FC5.3
GND: C50.1 C51.1 C53.1 C54.1 C55.1 C71.1 C72.1 C77.1 C78.1 FC5.2 FC6.2 R56.1 R57.1 R58.1 R75.1 U16.4(GND) U16.13(PAD)
PwrGd_4p3V_LDO: R74.2 ; port PwrGd_4p3V_LDO
NetC52_1: C52.1 U16.10(C1+)
NetC52_2: C52.2 U16.9(C1-)
NetC53_2: C53.2 D5.1(K) R53.2 U16.6(OUT-)
NetC54_2: C54.2 U16.5(CPOUT)
NetC55_2: C55.2 R55.2 R59.1 U16.11(OUT+)
NetD5_2: D5.2(A) R54.2
NetFC5_1: FC5.1 R54.1 R58.2 TP9.1
NetFC6_1: FC6.1 R59.2 TP8.1
NetR53_1: R53.1 R56.2 U16.7(FB-)
NetR55_1: R55.1 R57.2 U16.2(FB+)
NetR73_1: R73.1 R74.1 R75.2 U16.8(EN-) U16.12(EN+)

Not connected (* = marked no-connect by the designer): U16 1(PGOOD)*

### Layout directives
net class Power; net class ADC_Power: 3p9V_LMH, -1p1V_LMH

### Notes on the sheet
- Amplifier Power LDO

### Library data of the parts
C50 C53-C55 = capcc03657: CAP CER 10UF 10V X5R 0603; Manufacturer: KYOCERA AVX; CompType: Capacitor Ceramic; Tolerance: ±10%; SizeX_mm: 1.6; SizeY_mm: 0.81; SizeZ_mm: 0.94
C51 = capcc03112: CAP CER 2.2UF 10V X5R 0402; Manufacturer: TDK Corporation; CompType: Capacitor Ceramic; Tolerance: ±10%; SizeX_mm: 1; SizeY_mm: 0.5; SizeZ_mm: 0.55
C52 = capcc09264: CAP CER 1UF 10V X5R 0201; Manufacturer: Murata Electronics; CompType: Capacitor Ceramic; Tolerance: ±20%; SizeX_mm: 0.6; SizeY_mm: 0.3; SizeZ_mm: 0.33
C71 C72 C77 C78 = capcc09406: as C1 on sheet EVM Power
D5 = RBR3LAM40ATR: Diode 40 V 3A Surface Mount PMDTM; Manufacturer: Rohm Semiconductor; UniqueID: cmp00438
FC5 FC6 = dcp00001: as FC1 on sheet ADC Power
R53 = RSMD040201564: RES SMD 23.2KOHM 0.1% 1/16W 0402; Manufacturer: Panasonic Electronic Components; CompType: Resistor SMD; Power (Watts): 0.063W, 1/16W; Temperature Coefficient: ±25ppm/°C; SizeX_mm: 1; SizeY_mm: 0.5; SizeZ_mm: 0.4
R54 R58 = CMP-0016044-3: RES, 0, 5%, 0.75 W, AEC-Q200 Grade 0, 2010; Manufacturer: Vishay-Dale; Power_W: 750mW; TempCo: ppm/C; Value_Code: 0000; Value: 0; EIA_Code: E24; SizeX_mm: 5; SizeY_mm: 2.5; SizeZ_mm: 1.66; Value2: 0.75W; SizeArea_mm2: 12.5; AEC Qualified: Y; AEC Category: Q200
R55 = RSMD040202194: RES SMD 324 OHM 0.1% 1/16W 0402; Manufacturer: Panasonic Electronic Components; CompType: Resistor SMD; Power (Watts): 0.063W, 1/16W; Temperature Coefficient: ±25ppm/°C; SizeX_mm: 1; SizeY_mm: 0.5; SizeZ_mm: 0.4
R56 R57 = RSMD040200357: RES SMD 100K OHM 0.1% 1/16W 0402; Manufacturer: Panasonic Electronic Components; CompType: Resistor SMD; Power (Watts): 0.063W, 1/16W; Temperature Coefficient: ±25ppm/°C; SizeX_mm: 1; SizeY_mm: 0.5; SizeZ_mm: 0.4
R59 = RSMD080510615: RES SMD 0 OHM JUMPER 1/8W 0805; Manufacturer: Panasonic Electronic Components; CompType: Resistor SMD; Power (Watts): 0.125W, 1/8W; SizeX_mm: 2; SizeY_mm: 1.25; SizeZ_mm: 0.7
R73 = RSMD040200314: as R6 on sheet EVM Power
R74 R75 = RSMD040200001: as R17 on sheet ADC Power DC-DC
TP8 = cmp00045: Test Point, Multipurpose, Blue, TH; Manufacturer: Keystone
TP9 = cmp00042: Test Point, Multipurpose, White, TH; Manufacturer: Keystone
U16 = LM27762DSS: Low-Noise Positive- and Negative-Output Charge Pump With Integrated LDO; Manufacturer: Texas Instruments; UniqueID: cmp00189; CompType: Switcher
